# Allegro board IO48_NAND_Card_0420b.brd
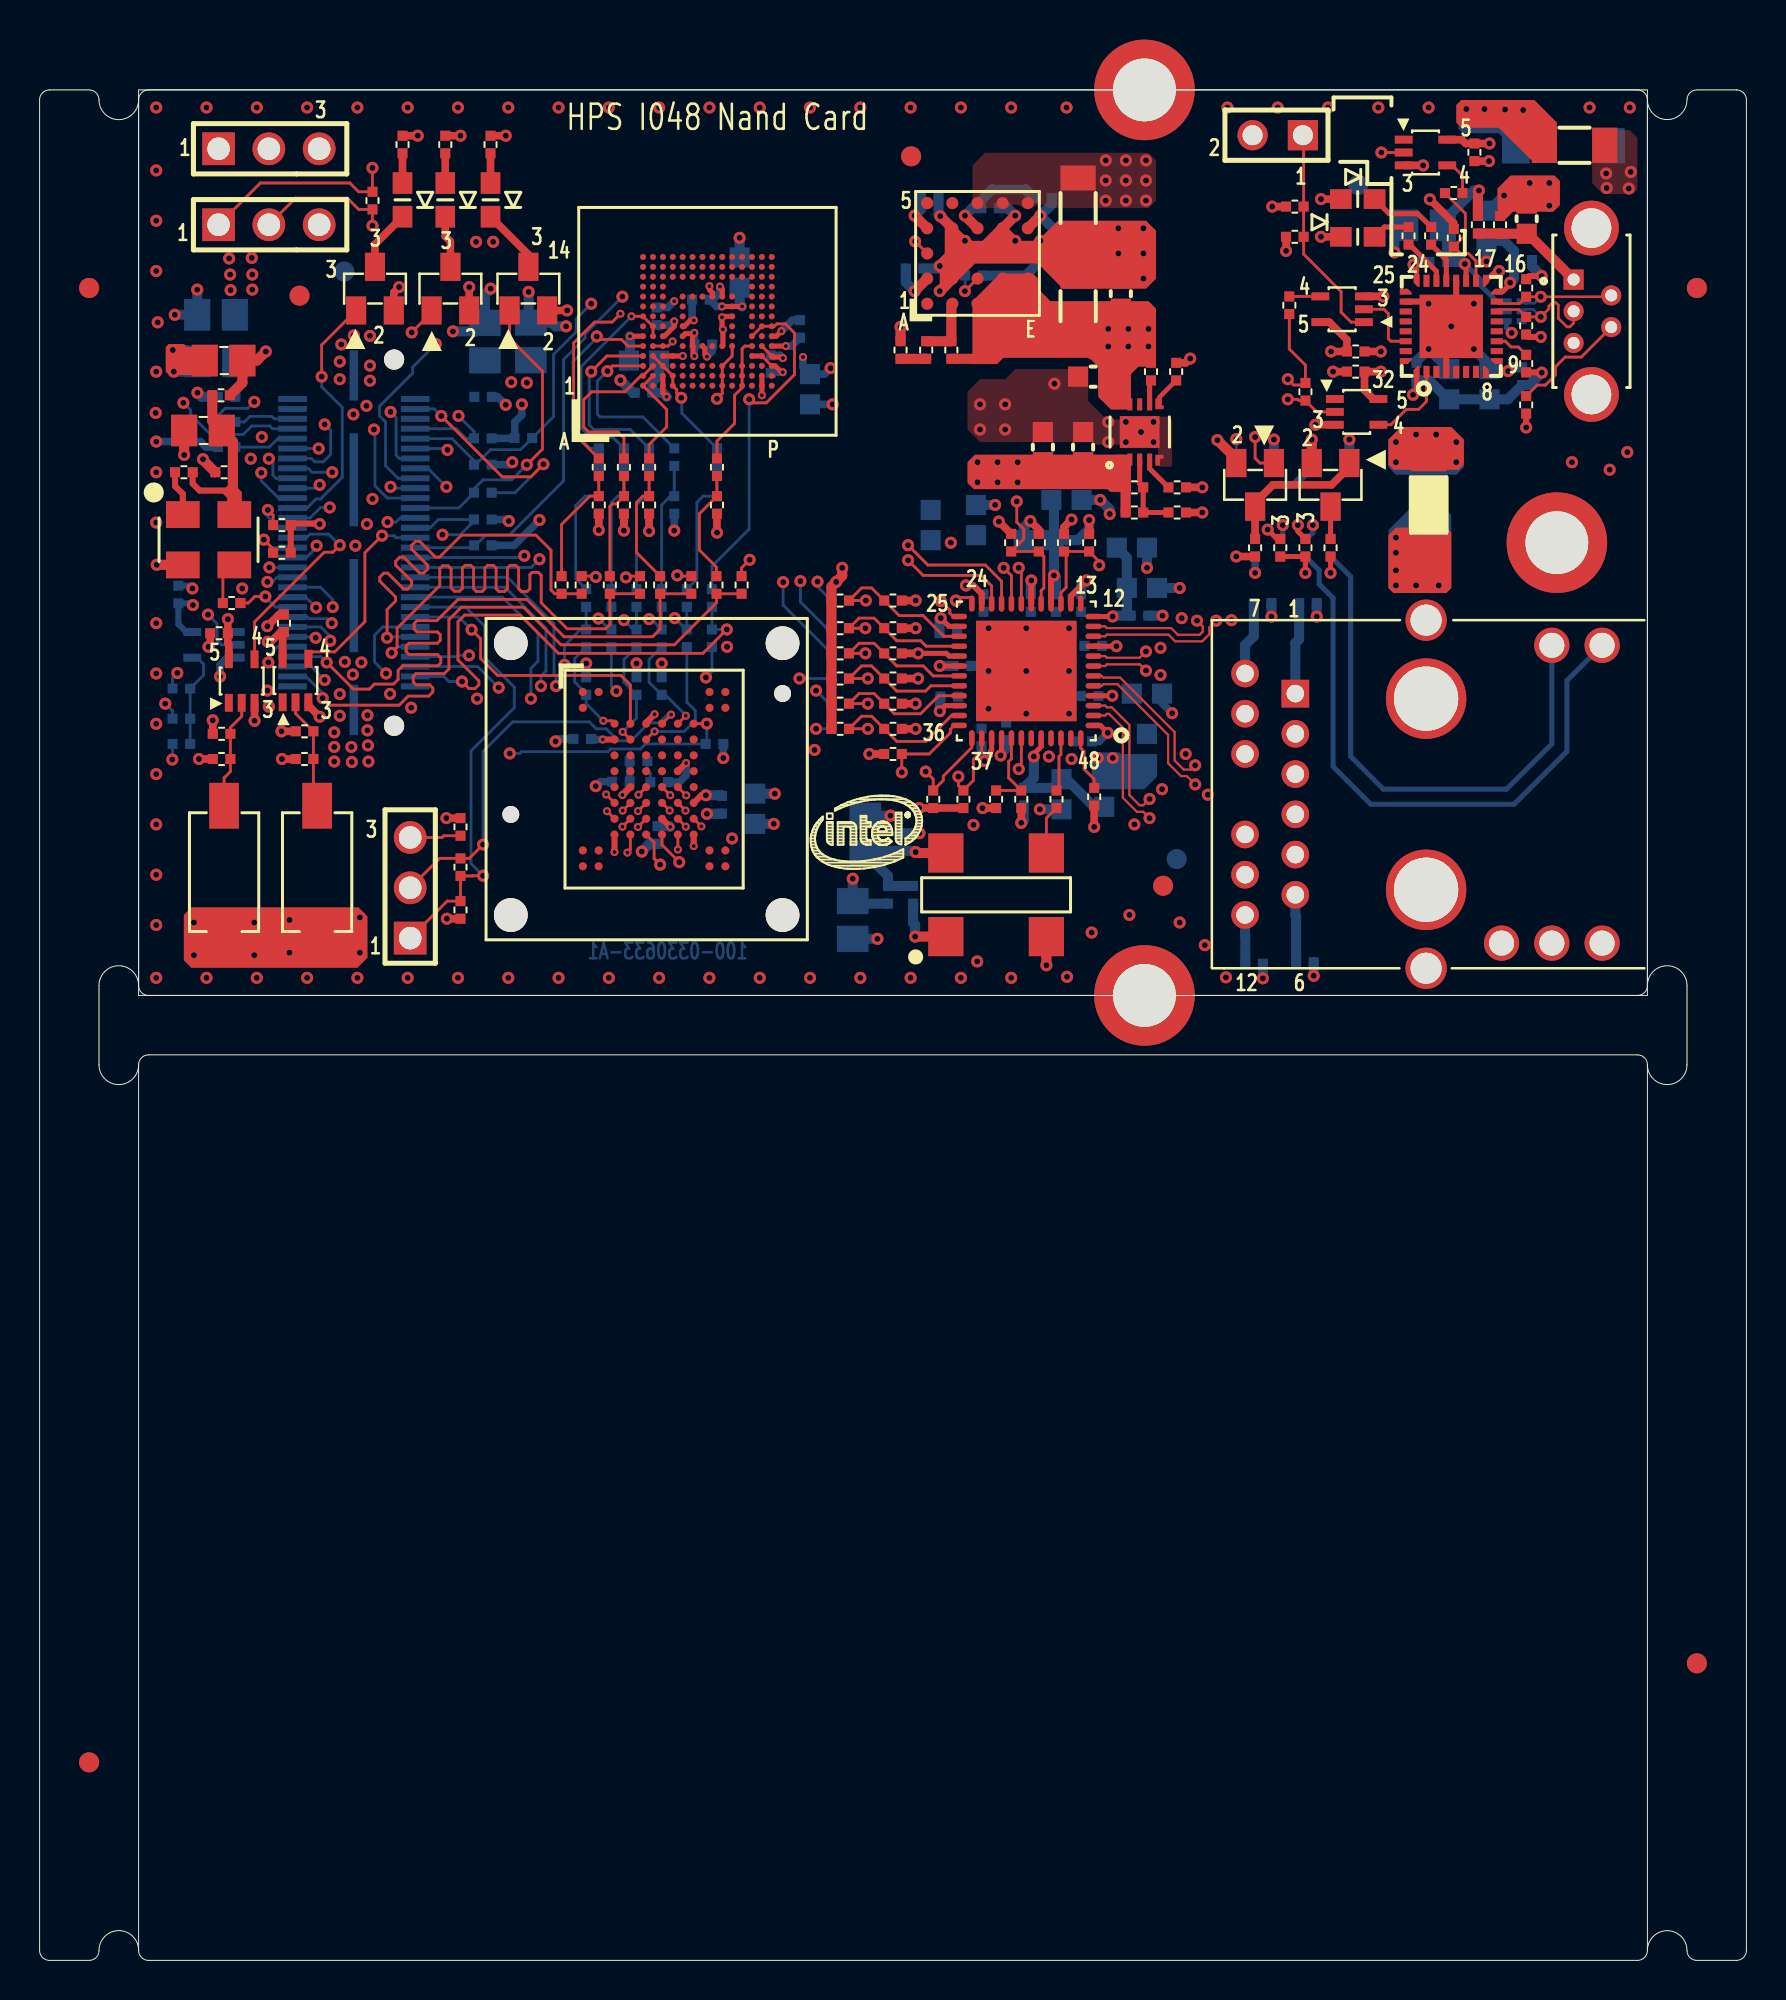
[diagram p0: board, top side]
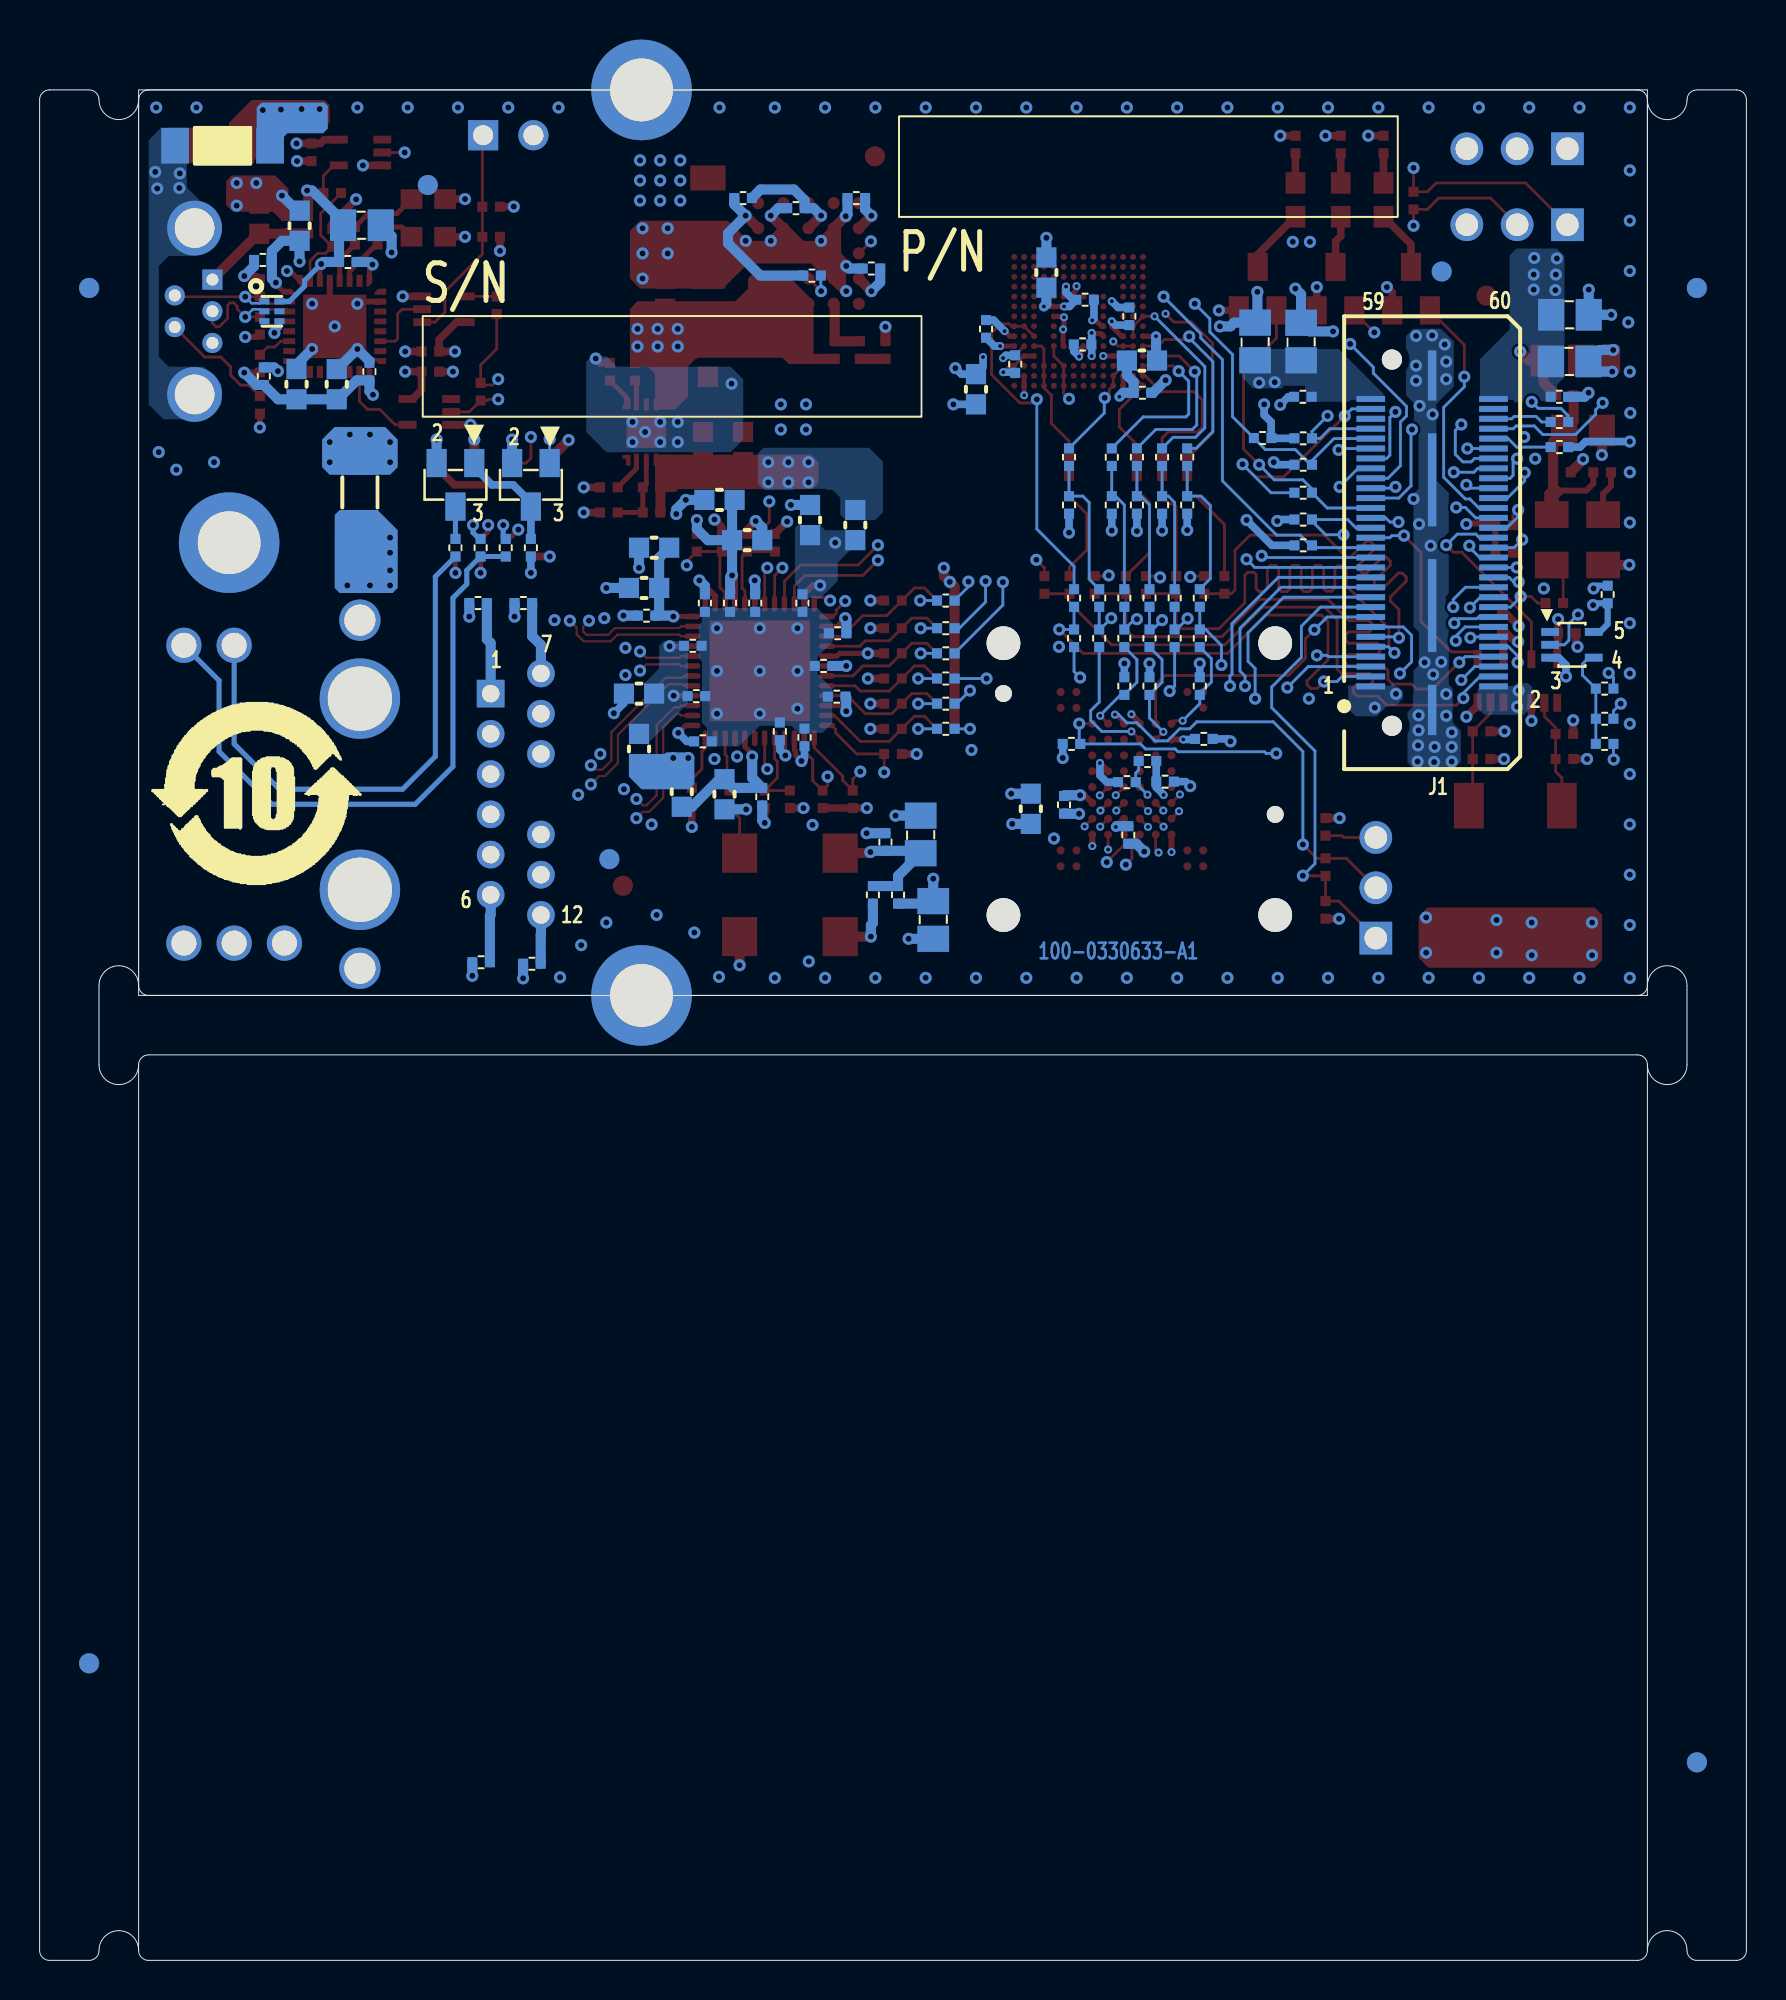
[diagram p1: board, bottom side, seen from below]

Outline 86.2 x 94.44 mm; copper layers: TOP, L2_GND, L3_SIG, L4_GND, L5_PWR, L6_SIG, L7_GND, BOTTOM. Coordinates in mm from the lower left corner of the outline.
Outline path: 5,49.22 arc(4,50.22) 3,49.22 3,45.22 arc(4,44.22) 5,45.22 ; 5,49.22 5,93.94 ; 5,49.22 arc(5.15,48.87) 5.5,48.72 80.7,48.72 arc(81.05,48.87) 81.2,49.22 ; 5,0.5 arc(3.99,1.5) 3,0.48 arc(2.85,0.14) 2.5,0 0.5,0 arc(0.15,0.15) 0,0.5 0,93.94 arc(0.15,94.29) 0.5,94.44 2.5,94.44 arc(2.85,94.29) 3,93.94 arc(4,92.94) 5,93.94 ; 5,0.5 5,45.22 ; 5,0.5 arc(5.15,0.15) 5.5,0 80.7,0 arc(81.05,0.15) 81.2,0.5 ; 5,93.94 arc(5.15,94.29) 5.5,94.44 80.7,94.44 arc(81.05,94.29) 81.2,93.94 ; 5,45.22 arc(5.15,45.57) 5.5,45.72 80.7,45.72 arc(81.05,45.57) 81.2,45.22 ; 81.2,93.94 81.2,49.22 ; 81.2,93.94 arc(82.21,92.94) 83.2,93.96 arc(83.35,94.3) 83.7,94.44 85.7,94.44 arc(86.05,94.29) 86.2,93.94 86.2,0.5 arc(86.05,0.15) 85.7,0 83.7,0 arc(83.35,0.15) 83.2,0.5 arc(82.2,1.5) 81.2,0.5 ; 81.2,45.22 81.2,0.5 ; 81.2,45.22 arc(82.2,44.22) 83.2,45.22 83.2,49.22 arc(82.2,50.22) 81.2,49.22 ; 5,94.44 5,48.72 81.2,48.72 81.2,94.44 5,94.44

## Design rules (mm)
net group ENET_1.8V_DVDDH: nets E_RXD2 ENET_RXD2
net group ENET_RX_CLK: nets E_RX_CLK ENET_RX_CLK
net group ENET_RX_DV: nets E_RX_DV ENET_RX_DV
net group ENET_RXD0: nets E_RXD0 ENET_RXD0
net group ENET_RXD1: nets E_RXD1 ENET_RXD1
net group ENET_RXD3: nets E_RXD3 ENET_RXD3
net group MDI_HPS_N0: nets MDI_HPS_N0 MDI_HPS_P0
net group MDI_HPS_N1: nets MDI_HPS_N1 MDI_HPS_P1
net group MDI_HPS_N2: nets MDI_HPS_N2 MDI_HPS_P2
net group MDI_HPS_N3: nets MDI_HPS_N3 MDI_HPS_P3
net group UART_X: nets UART_RX UART_TX
net group UART_X_LED: nets UART_RX_LED UART_TX_LED
net group USB_UART_DM: nets USB_UART_DM USB_UART_DP
net group EMMC_CLK: nets EMMC_CLK NAND_ADQ0 NAND_ADQ0_EMMC_CLK
net group EMMC_CMD: nets EMMC_CMD EMMC_COMMAND NAND_ADQ1 NAND_ADQ1_EMMC_CMD
net group EMMC_D0: nets EMMC_D0 EMMC_DAT0 NAND_WEN NAND_WEN_EMMC_D0
net group EMMC_D1: nets EMMC_D1 EMMC_DAT1 NAND_REN NAND_REN_EMMC_D1
net group EMMC_D2: nets EMMC_D2 EMMC_DAT2 NAND_WPN NAND_WPN_EMMC_D2
net group EMMC_D3: nets EMMC_D3 EMMC_DAT3 NAND_ADQ2 NAND_ADQ2_EMMC_D3
net group EMMC_D4: nets EMMC_D4 EMMC_DAT4 NAND_ADQ3 NAND_ADQ3_EMMC_D4
net group EMMC_D5: nets EMMC_D5 EMMC_DAT5 NAND_CLE NAND_CLE_EMMC_D5
net group EMMC_D6: nets EMMC_D6 EMMC_DAT6 NAND_ADQ4 NAND_ADQ4_EMMC_D6
net group EMMC_D7: nets EMMC_D7 EMMC_DAT7 NAND_ADQ5 NAND_ADQ5_EMMC_D7
net group ENET: nets ENET_INTN
net group POWER: nets LT_INTVCC N134005839 N134232203 N134273619 N134273639 N134279761 N134279929 N134279963 N134279979 N134280029 N134318194

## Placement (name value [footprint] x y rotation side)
C1  4.7uF  [0805]  22.49 81.73 0 bottom
C2  0.1uF  [0402]  22.4 78.95 90 bottom
C3  4.7uF  [0805]  8.93 80.73 90 bottom
C4  0.1uF  [0402]  9.44 78.95 270 bottom
C5  0.01uF  [0402]  61.34 50.32 270 bottom
C6  0.01uF  [0402]  63.9 50.4 270 bottom
C7  0.01uF  [0402]  64.05 68.53 270 bottom
C8  0.01uF  [0402]  61.77 68.53 270 bottom
C11  22uF  [0603]  55.67 69.29 0 bottom
C13  0.1uF  [0402]  55.55 67.9 90 bottom
C15  22uF  [0603]  50.47 71.71 180 bottom
C17  0.1uF  [0402]  51.33 68.53 0 bottom
C18  22uF  [0603]  51.61 58.88 270 bottom
C20  0.1uF  [0402]  49.7 58.75 0 bottom
C23  22uF  [0603]  55.93 63.96 0 bottom
C25  0.1uF  [0402]  53.21 66.37 270 bottom
C26  22uF  [0603]  52.7 76.41 90 top
C28  2.2uF  [0603]  50.67 76.41 90 top
C29  22uF  [0603]  47.29 72.72 90 bottom
C31  0.1uF  [0402]  47.57 61.75 180 bottom
C36  39pF  [0402]  75.08 84.44 180 top
C37  39pF  [0402]  75.08 82.54 0 top
C38  0.1uF  [0402]  74.93 85.85 90 bottom
C39  2.2uF  [0603]  73.07 87.58 90 bottom
C40  0.1uF  [0402]  69.54 80.22 180 bottom
C41  2.2uF  [0603]  71.19 79.58 90 bottom
C42  0.1uF  [0402]  70.63 85.75 270 bottom
C43  4.7uF  [0805]  69.92 87.61 90 bottom
C44  0.01uF  [0402]  73.76 87.63 0 top
C45  0.1uF  [0402]  31.21 56.82 0 bottom
C46  0.1uF  [0402]  34.46 58.35 0 bottom
C47  0.1uF  [0402]  27.4 61.67 270 bottom
C48  0.1uF  [0402]  29.36 59.51 270 bottom
C49  1uF  [0603]  30.53 80.77 180 bottom
C50  0.1uF  [0402]  30.5 79.15 270 bottom
C51  2.2uF  [0603]  35.35 85.22 90 bottom
C52  0.22uF  [0402]  33.4 83.85 90 bottom
C53  2.2uF  [0603]  38.91 79.33 270 bottom
C54  0.22uF  [0402]  31.16 83.01 0 bottom
C55  0.1uF  [0402]  13.38 60.66 90 top
C56  0.1uF  [0402]  9.19 60.66 90 top
C59  0.1uF  [0402]  72.46 91.29 0 top
C70  0.1uF  [0402]  12.34 67.52 180 top
C76  2.2uF  [0603]  54.61 84.15 90 top
C900  100pF  [0402]  46.05 81.31 180 top
C909  0.1uF  [0402]  7.01 68.96 0 bottom
C914  22uF  [0603]  73.22 79.58 90 bottom
C915  22uF  [0603]  75.1 87.94 90 top
C917  10uF  [1206]  52.45 88.47 270 top
C922  0.01uF  [0402]  44.19 85.42 270 bottom
C924  10uF  [C0805]  41.07 52.53 180 bottom
C925  0.1uF  [0402]  43.48 56.47 180 bottom
C927  10uF  [C0805]  41.7 56.85 0 bottom
C928  22uF  [0603]  53.21 79.96 180 top
C929  1nF  [0402]  57.4 80.22 0 top
C930  120pF  [0402]  55.29 74.37 270 top
C931  0.1uF  [0402]  53.03 63.83 270 bottom
C932  0.1uF  [0402]  46.61 65.36 90 bottom
C933  0.1uF  [0402]  45.89 67.01 90 bottom
C934  0.1uF  [0402]  47.67 68.53 0 bottom
C935  0.1uF  [0402]  50.06 68.53 0 bottom
C936  0.1uF  [0402]  52.6 68.53 0 bottom
C937  0.1uF  [0402]  52.7 61.55 270 bottom
C938  0.1uF  [0402]  45.94 63.81 90 bottom
C939  0.1uF  [0402]  48.81 62.05 180 bottom
C940  1000PF  [1808]  76.96 91.62 0 bottom
C942  1000PF  [1808]  70.15 73.48 270 top
C943  0.1uF  [0402]  66.47 80.22 270 top
C944  0.1uF  [0402]  66.47 81.23 90 top
C949  47uF  [1206]  52.45 83.52 270 top
C953  0.1uF  [0402]  9.32 75.14 90 top
C954  10uF  [C0805]  9.29 80.77 270 top
C955  10uF  [C0805]  8.25 77.24 270 top
C956  0.1uF  [0402]  9.06 67.01 270 top
C957  2.2uF  [0603]  36.14 58.14 270 bottom
C958  0.22uF  [0402]  33.52 81.59 270 bottom
C959  0.22uF  [0402]  36.93 80.6 0 bottom
C960  0.22uF  [0402]  38.4 82.37 0 bottom
C961  4.7uF  [0805]  24.81 81.74 0 bottom
C962  4.7uF  [0805]  8.91 83.09 90 bottom
C964  0.1uF  [0402]  63.93 71.33 0 top
C965  0.1uF  [0402]  63.93 71.33 0 bottom
D1  GREEN_LED  [LED_0603]  66.57 87.02 0 top
D2  GREEN_LED  [LED_0603]  66.57 88.93 0 top
D3  GREEN_LED  [LED_0603]  20.49 88.89 270 top
D4  GREEN_LED  [LED_0603]  18.33 88.89 270 top
D5  GREEN_LED  [LED_0603]  22.77 88.89 270 top
J1  QTH-030-02-L-D-A  [QTH-030]  15.87 71.58 90 bottom
J2  HEADER, 1x3-PIN  [CONN_TSW_103_07_L_S]  9.04 91.47 0 top
J3  ENET_L829-1J1T-43  [BEL_L829-1J1T-43]  63.42 63.96 270 top
J7  USB MINI-B-SMT Vertical  [MINI_USB_SMTB]  78.37 83.26 90 top
J9  CON2  [HDR2X1_100MIL]  63.8 92.15 180 top
J10  HEADER, 1x3-PIN  [CONN_TSW_103_07_L_S]  9.04 87.63 0 top
J11  HEADER, 1x3-PIN  [CONN_TSW_103_07_L_S]  18.72 51.62 90 top
L1  3A, 30 Ohm FB  [IND_0603]  55.16 71.33 180 bottom
L2  3A, 30 Ohm FB  [IND_0603]  51.86 73.74 180 bottom
L3  3A, 30 Ohm FB  [IND_0603]  53.77 59.01 270 bottom
L4  3A, 30 Ohm FB  [IND_0603]  55.93 61.17 90 bottom
L5  3A, 30 Ohm FB  [IND_0603]  45 72.47 270 bottom
L6  742792780  [0402]  72.64 87.63 0 top
L7  742792780  [0402]  42.85 53.8 0 bottom
L8  742792780  [0402]  9.17 79.02 270 top
L10  742792780  [0402]  65.2 71.33 180 bottom
L11  742792780  [0402]  65.2 71.33 0 top
NOREF  #  [unnamed]  55.8 94.44 0 top
NOREF#2  -  [unnamed#2]  44.01 91.09 0 top
NOREF#3  -  [unnamed#2]  2.5 84.44 0 top
NOREF#4  -  [unnamed#2]  83.7 84.44 0 top
NOREF#5  -  [unnamed#2]  13.13 84.05 0 top
NOREF#6  -  [unnamed#2]  83.7 15 0 top
NOREF#7  #  [unnamed]  55.8 48.72 0 top
NOREF#8  -  [unnamed#2]  56.74 54.26 0 top
NOREF#9  #  [unnamed]  76.63 71.58 0 top
NOREF#10  -  [unnamed#2]  2.5 10 0 top
NOREF#11  -  [unnamed#2]  83.7 15 180 bottom
NOREF#12  -  [unnamed#2]  15.39 85.27 180 bottom
NOREF#13  -  [unnamed#2]  66.59 89.64 180 bottom
NOREF#14  -  [unnamed#2]  57.43 55.6 180 bottom
NOREF#15  -  [unnamed#2]  2.5 10 180 bottom
NOREF#16  -  [unnamed#2]  2.5 84.44 180 bottom
NOREF#17  -  [unnamed#2]  83.7 84.44 180 bottom
Q1  FDV305N  [SOT23]  20.75 84.41 0 top
Q2  FDV305N  [SOT23]  16.94 84.41 0 top
Q3  FDV305N  [SOT23]  24.68 84.41 0 top
Q4  FDV305N  [SOT23]  61.39 74.5 180 top
Q5  FDV305N  [SOT23]  65.2 74.5 180 top
Q6  FDV305N  [SOT23]  61.39 74.5 0 bottom
Q7  FDV305N  [SOT23]  65.2 74.5 0 bottom
R1  0  [0402]  9.44 76.41 90 bottom
R2  4.7K  [0402]  43.1 60.91 90 top
R4  4.7K  [0402]  45.13 58.63 180 top
R6  33  [0402]  40.43 62.18 90 bottom
R7  4.7K  [0402]  46.66 58.63 180 top
R8  220  [0402]  62.66 71.33 180 bottom
R9  33  [0402]  40.43 63.45 90 bottom
R10  33  [0402]  40.43 64.72 90 bottom
R11  33  [0402]  40.43 65.99 90 bottom
R12  33  [0402]  40.43 67.26 90 bottom
R13  33  [0402]  40.43 68.66 90 bottom
R14  220  [0402]  62.66 71.33 0 top
R15  12.1K  [0402]  53.26 58.75 0 top
R16  DNI  [0402]  53.01 71.58 0 top
R17  4.7K  [0402]  51.74 71.58 180 top
R18  10K  [0402]  44.12 53.8 180 bottom
R19  33  [0402]  51.35 58.63 180 top
R20  DNI  [0402]  49.07 71.58 0 top
R21  4.7K  [0402]  50.47 71.58 180 top
R23  4.7K  [0402]  40.43 68.66 90 top
R24  DNI  [0402]  43.1 68.66 90 top
R25  4.7K  [0402]  40.43 67.26 90 top
R26  DNI  [0402]  43.1 67.26 90 top
R27  4.7K  [0402]  40.43 65.99 90 top
R28  DNI  [0402]  43.1 65.99 90 top
R29  4.7K  [0402]  40.43 64.72 90 top
R30  DNI  [0402]  43.1 64.72 90 top
R31  DNI  [0402]  40.43 63.45 90 top
R32  4.7K  [0402]  43.1 63.45 90 top
R33  4.7K  [0402]  40.43 62.18 90 top
R34  DNI  [0402]  43.1 62.18 90 top
R35  4.7K  [0402]  48.31 58.63 180 top
R36  DNI  [0402]  49.58 58.63 0 top
R39  1.87K  [0402]  57.45 73.1 270 top
R42  0  [0402]  74.88 79.99 180 bottom
R46  0  [0402]  75.08 78.54 0 top
R48  220  [0402]  69.13 87.07 180 top
R49  220  [0402]  70.28 87.07 180 top
R50  10K  [0402]  75.08 80.62 0 top
R52  0  [0402]  33.96 66.75 180 bottom
R53  0  [0402]  33.96 68.79 0 bottom
R54  0  [0402]  34.18 69.45 180 top
R55  0  [0402]  35.45 69.45 180 top
R56  0  [0402]  32.91 69.45 180 top
R57  0  [0402]  31.34 69.45 180 top
R58  0  [0402]  30.32 69.45 180 top
R59  0  [0402]  28.8 69.45 180 top
R60  0  [0402]  27.38 69.45 180 top
R62  0  [0402]  26.36 69.45 180 top
R64  0  [0402]  28.88 66.75 180 bottom
R65  0  [0402]  28.88 68.79 0 bottom
R66  0  [0402]  27.61 66.75 180 bottom
R67  0  [0402]  27.61 68.79 0 bottom
R68  0  [0402]  31.42 66.75 180 bottom
R69  0  [0402]  31.42 68.79 0 bottom
R72  0  [0402]  30.15 66.75 180 bottom
R74  0  [0402]  30.15 68.79 0 bottom
R77  0  [0402]  32.69 66.75 180 bottom
R79  0  [0402]  32.69 68.79 0 bottom
R83  10K  [0402]  34.21 73.48 0 top
R86  220  [0402]  20.49 91.68 0 top
R87  220  [0402]  18.33 91.68 0 top
R88  220  [0402]  22.77 91.68 0 top
R89  10K  [0402]  13.38 62.05 270 top
R90  10K  [0402]  9.19 61.93 270 top
R91  10K  [0402]  7.29 75.14 270 top
R102  10K  [0402]  27.61 64.34 0 bottom
R103  10K  [0402]  21.26 53.04 0 top
R104  10K  [0402]  30.15 64.34 0 bottom
R105  10K  [0402]  31.42 64.34 0 bottom
R456  13.3K  [0402]  44.78 81.31 180 top
R667  324K  [R0402]  44.95 88.98 90 bottom
R668  0  [0402]  43.48 81.31 0 top
R671  10K  [0402]  47.19 85.07 270 bottom
R675  4.7K  [0402]  22.38 76.85 90 bottom
R681  DNI  [0402]  9.44 77.68 90 bottom
R682  DNI  [0402]  22.38 74.1 90 bottom
R686  4.7K  [0402]  22.38 72.75 90 bottom
R687  4.7K  [0402]  22.38 71.44 90 bottom
R688  4.7K  [0402]  12.24 71.07 270 top
R698  1.00K  [0402]  22.38 75.52 90 bottom
R699  2.61K  [0402]  55.29 73.1 90 top
R5256  4.7K  [0402]  12.24 72.47 270 top
R5257  1.00K  [0402]  31.29 59.49 270 bottom
R5258  10K  [0402]  34.08 61.42 270 bottom
R5259  1.00K  [0402]  50.67 88.98 90 bottom
R5262  4.7K  [0402]  56.13 80.22 180 top
R5265  4.7K  [0402]  57.45 74.37 90 top
R5266  1M  [1206]  77.52 91.65 180 top
R5268  1M  [1206]  70.02 74.12 90 bottom
R5269  1.00K  [0402]  63.39 87.02 90 top
R5270  DNI  [0402]  71.42 89.23 270 top
R5271  4.7K  [0402]  71.42 86.97 0 top
R5275  DNI  [0402]  48 88.47 90 bottom
R5276  33  [0402]  7.16 61.42 90 bottom
R5277  33  [0402]  7.16 62.69 90 bottom
R5278  33  [0402]  7.16 64.21 90 bottom
R5279  10K  [0402]  32.05 73.48 180 bottom
R5280  10K  [0402]  28.24 73.48 180 bottom
R5281  10K  [0402]  30.78 73.48 180 bottom
R5282  10K  [0402]  30.78 73.48 0 top
R5283  10K  [0402]  29.51 73.48 0 top
R5284  10K  [0402]  34.21 73.48 180 bottom
R5285  10K  [0402]  28.24 73.48 0 top
R5286  10K  [0402]  29.51 73.48 180 bottom
R5287  DNI  [0402]  63.39 88.55 270 top
R5288  DNI  [0402]  63.93 79.2 180 top
R5289  33  [0402]  9.7 68.53 90 top
R5300  33  [0402]  63.12 83.57 180 top
R5301  33  [0402]  32.05 75.9 0 bottom
R5302  33  [0402]  30.78 75.9 0 bottom
R5303  33  [0402]  28.24 75.9 0 bottom
R5304  33  [0402]  30.78 75.39 180 top
R5305  33  [0402]  29.51 75.39 180 top
R5306  33  [0402]  34.21 75.9 0 bottom
R5307  33  [0402]  28.24 75.39 180 top
R5308  33  [0402]  29.51 75.9 0 bottom
R5309  33  [0402]  34.21 75.39 180 top
R5310  DNI  [0402]  30.25 60.56 270 bottom
R5311  1.00K  [0402]  61.39 71.33 180 top
R5312  1.00K  [0402]  61.39 71.33 0 bottom
R5313  10K  [0402]  21.26 57.23 0 top
R5314  DNI  [0402]  16.81 88.85 0 top
R5315  DNI  [0402]  21.26 55.2 180 top
R5316  DNI  [0402]  24.43 76.86 270 bottom
S1  PB Switch  [WURTH_6X3P5_TACT_SWITCH]  14.02 54.94 90 top
S2  PB Switch  [WURTH_6X3P5_TACT_SWITCH]  9.32 54.94 90 top
U1  KSZ9031RN  [QFN48]  49.83 65.1 180 top
U5  FT232R  [QFN32-FTDI]  71.29 82.5 90 top
U6  TPD4S012DRYR  [SON6]  74.47 83.26 270 bottom
U7  MT29F8G16ADBDAH4-AIT:D  [VFBGA63_SOCKET]  31.03 59.64 0 top
U8  MTFC8GAKAJCN-4M IT  [VFBGA-153]  33.73 82.76 90 top
U14  SN74AUP1G17DCK  [SC70_TI]  12.92 64.62 0 top
U15  LTM4623EY#PBF  [BGA25]  47.37 86.18 90 top
U62  EY1501DI-ADJ  [DFN-10]  55.56 77.17 90 top
U63  SN74AUP1G126DCK  [SC70_TI]  65.78 83.37 90 top
U64  SN74AUP1T17DCKR  [SC70_TI]  69.99 91.28 270 top
U65  SN74AUP1T17DCKR  [SC70_TI]  66.52 78.18 270 top
U68  SN74AUP1G17DCK  [SC70_TI]  8.81 66.42 270 bottom
U69  SN74AUP1G17DCK  [SC70_TI]  10.21 64.59 0 top
Y1  25MHz  [OSC3250]  8.53 71.73 0 top
Y2  25MHz  [OSC7050]  48.31 53.8 0 top

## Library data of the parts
C1-C8 C13 C17 C20 C25 C31 C38 C40 C42-C48 C50 C52 C54-C56 C59 C70 C900 C909 C922 C924 C925 C927 C929-C939 C943 C944 C953-C956 C958-C962 C964 C965 = CAP: Tolerance: TOL; User Part Number: PART#
C11 C15 C18 C23 C26 C28 C29 C39 C41 C49 C51 C53 C76 C914 C915 C928 C957 = CAP: User Part Number: *; Tolerance: *
C36 C37 = Cap 39PF 5% 50V 0402: Tolerance: TOL; User Part Number: PART#
C917 C949 = CAP: Tolerance: *; User Part Number: *
C940 C942 = CAP: Tolerance: ?; User Part Number: CC4520R01A
D1-D5 = LED_WURTH: Tolerance: *; User Part Number: *
J1 = HEADER 30X2_0
J2 J10 J11 = HEADER, 1x3-PIN: User Part Number: *
J3 = ENET_L829-1J1T-43_2: Tolerance: *; User Part Number: *
J7 = USB_MINI_B_SMT
J9 = CON2: User Part Number: *
L1-L5 = IND Ferrite 0603 3A/30 Ohms: Tolerance: *; User Part Number: *
L6-L8 L10 L11 = BEAD_FERRITE_SM: Tolerance: TOL; User Part Number: PART#
NOREF = -: User Part Number: ***********; Tolerance: ?
NOREF#7 NOREF#9 = -: Tolerance: ?; User Part Number: ***********
Q1-Q7 = NMOS_3Pin: Tolerance: *; User Part Number: *
R1 R2 R4 R7 R8 R14-R21 R23 R24 R26-R36 R39 R42 R46 R48-R50 R83 R86-R91 R102-R105 R668 R671 R675 R681 R682 R686-R688 R698 R5256-R5259 R5262 R5265 R5269-R5271 R5275-R5289 R5300 R5310-R5316 = RESISTOR: Tolerance: TOL; User Part Number: PART#
R6 R9-R13 R5301-R5309 = RESISTOR: Tolerance: TOL; User Part Number: PART#; signal model: RESISTOR_0402_33_33
R25 = RESISTOR: Tolerance: TOL; User Part Number: PART#; signal model: RESISTOR_0402_4.7K_4.7K
R52-R60 R62 R64-R69 R72 R74 R77 R79 = RESISTOR: Tolerance: TOL; User Part Number: PART#; signal model: RESISTOR_0402_0_0
R456 = RESISTOR_0402: Tolerance: TOL; User Part Number: PART#
R667 = Resistor, 0402: User Part Number: PART#; Tolerance: TOL
R699 = R: Tolerance: TOL; User Part Number: PART#
R5266 R5268 = RESISTOR: Tolerance: *; User Part Number: *
S1 S2 = TS-A02SA-2-S100_0: User Part Number: *
U1 = KSZ9031RN_4: User Part Number: *
U5 = FT232R_2: User Part Number: *
U6 = TPD4S012DRYR: User Part Number: *
U7 = MT29F8G16ABBCAH4-IT_1
U8 = MTFC8GAKAJCN-4M IT
U14 U64 U65 U68 U69 = SN74AUP1G17DCK
U15 = LTM4623EV#PBF
U62 = EY1501DI-ADJ
U63 = SN74AUP1G126DCK
Y1 = OSC_ALT
Y2 = OSC_ALT: User Part Number: *; Tolerance: *

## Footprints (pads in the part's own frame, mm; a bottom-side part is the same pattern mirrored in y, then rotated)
0402
  rect 0.508x0.508 smd: 1(0,0.445) 2(0,-0.445)
0603
  rect 1.016x1.016 smd: 1(-0.762,0) 2(0.762,0)
0805
  rect 1.6x1.321 smd: 1(0,0.95) 2(0,-0.95)
1206
  rect 1.27x1.778 smd: 1(-1.524,0) 2(1.524,0)
1808
  rect 1.4x1.8 smd: 1(-2.4,0) 2(2.4,0)
BEL_L829-1J1T-43
  round 4.064 hole 3.251: (0.254,6.604) (9.906,6.604)
  rect 1.397x1.397 hole 0.889: 1(0,0)
  round 1.397 hole 0.889: 2(2.032,0) 3(4.064,0) 4(6.096,0) 5(8.128,0) 6(10.16,0) 7(-1.016,-2.54) 8(1.016,-2.54) 9(3.048,-2.54) 10(7.112,-2.54) 11(9.144,-2.54) 12(11.176,-2.54)
  round 1.778 hole 1.27: 13(-2.438,12.954) 14(-2.438,15.494) 15(12.598,10.414) 16(12.598,12.954) 17(12.598,15.494)
  round 2.083 hole 1.575: 18(-3.708,6.604) 19(13.868,6.604)
BGA25
  round 0.61 smd: A1(-2.54,2.54) A2(-1.27,2.54) A3(0,2.54) A4(1.27,2.54) A5(2.54,2.54) B1(-2.54,1.27) B2(-1.27,1.27) B3(0,1.27) B4(1.27,1.27) B5(2.54,1.27) C1(-2.54,0) C2(-1.27,0) C3(0,0) C4(1.27,0) C5(2.54,0) D1(-2.54,-1.27) D2(-1.27,-1.27) D3(0,-1.27) D4(1.27,-1.27) D5(2.54,-1.27) E1(-2.54,-2.54) E2(-1.27,-2.54) E3(0,-2.54) E4(1.27,-2.54) E5(2.54,-2.54)
C0805
  rect 1.6x1.321 smd: 1(0,0.95) 2(0,-0.95)
CONN_TSW_103_07_L_S
  rect 1.651x1.651 hole 1.143: 1(0,0)
  round 1.651 hole 1.143: 2(2.54,0) 3(5.08,0)
DFN-10
  custom 0.104x0.104 smd: 1(-1.425,1) 5(-1.425,-1) 6(1.425,-1) 10(1.425,1)
  rect 0.61x0.254 smd: 2(-1.395,0.5) 3(-1.395,0) 4(-1.395,-0.5) 7(1.395,-0.5) 8(1.395,0) 9(1.395,0.5)
  rect 1.6x2.007 smd: 11(0,0)
HDR2X1_100MIL
  rect 1.524x1.524 hole 1.016: 1(0,0)
  round 1.524 hole 1.016: 2(2.54,0)
IND_0603
  rect 1.016x1.016 smd: 1(-0.762,0) 2(0.762,0)
LED_0603
  rect 1.092x0.991 smd: A(-0.851,0) C(0.851,0)
MINI_USB_SMTB
  rect 1.016x1.016 hole 0.61: 1(1.6,0.9)
  round 1.016 hole 0.61: 2(0.8,-1) 3(0,0.9) 4(-0.8,-1) 5(-1.6,0.9)
  round 2.769 hole 2.007: 6(-4.2,0) 7(4.2,0)
OSC3250
  rect 1.7x1.35 smd: 1(-1.3,1.27) 2(-1.3,-1.27) 3(1.3,-1.27) 4(1.3,1.27)
OSC7050
  rect 1.778x1.981 smd: 1(-2.54,-2.109) 2(2.54,-2.109) 3(2.54,2.109) 4(-2.54,2.109)
QFN32-FTDI
  custom 0.075x0.075 smd: 1(-2.3,1.75) 8(-2.3,-1.75) 9(-1.75,-2.3) 16(1.75,-2.3) 17(2.3,-1.75) 24(2.3,1.75) 25(1.75,2.3) 32(-1.75,2.3)
  rect 0.61x0.305 smd: 2(-2.3,1.25) 3(-2.3,0.75) 4(-2.3,0.25) 5(-2.3,-0.25) 6(-2.3,-0.75) 7(-2.3,-1.25) 18(2.3,-1.25) 19(2.3,-0.75) 20(2.3,-0.25) 21(2.3,0.25) 22(2.3,0.75) 23(2.3,1.25)
  rect 0.305x0.61 smd: 10(-1.25,-2.3) 11(-0.75,-2.3) 12(-0.25,-2.3) 13(0.25,-2.3) 14(0.75,-2.3) 15(1.25,-2.3) 26(1.25,2.3) 27(0.75,2.3) 28(0.25,2.3) 29(-0.25,2.3) 30(-0.75,2.3) 31(-1.25,2.3)
  rect 3.2x3.2 smd: 33(0,0)
QFN48
  oval 0.813x0.279 smd: 1(-3.4,2.75) 2(-3.4,2.25) 3(-3.4,1.75) 4(-3.4,1.25) 5(-3.4,0.75) 6(-3.4,0.25) 7(-3.4,-0.25) 8(-3.4,-0.75) 9(-3.4,-1.25) 10(-3.4,-1.75) 11(-3.4,-2.25) 12(-3.4,-2.75) 25(3.4,-2.75) 26(3.4,-2.25) 27(3.4,-1.75) 28(3.4,-1.25) 29(3.4,-0.75) 30(3.4,-0.25) 31(3.4,0.25) 32(3.4,0.75) 33(3.4,1.25) 34(3.4,1.75) 35(3.4,2.25) 36(3.4,2.75)
  oval 0.279x0.813 smd: 13(-2.75,-3.4) 14(-2.25,-3.4) 15(-1.75,-3.4) 16(-1.25,-3.4) 17(-0.75,-3.4) 18(-0.25,-3.4) 19(0.25,-3.4) 20(0.75,-3.4) 21(1.25,-3.4) 22(1.75,-3.4) 23(2.25,-3.4) 24(2.75,-3.4) 37(2.75,3.4) 38(2.25,3.4) 39(1.75,3.4) 40(1.25,3.4) 41(0.75,3.4) 42(0.25,3.4) 43(-0.25,3.4) 44(-0.75,3.4) 45(-1.25,3.4) 46(-1.75,3.4) 47(-2.25,3.4) 48(-2.75,3.4)
  rect 5.08x5.08 smd: 49(0,0)
QTH-030
  round 1.016 hole 1.016 unplated: (-9.246,2.032) (9.246,2.032)
  rect 0.305x1.448 smd: 1(-7.256,3.099) 2(-7.256,-3.099) 3(-6.755,3.099) 4(-6.755,-3.099) 5(-6.255,3.099) 6(-6.255,-3.099) 7(-5.754,3.099) 8(-5.754,-3.099) 9(-5.254,3.099) 10(-5.254,-3.099) 11(-4.754,3.099) 12(-4.754,-3.099) 13(-4.253,3.099) 14(-4.253,-3.099) 15(-3.753,3.099) 16(-3.753,-3.099) 17(-3.252,3.099) 18(-3.252,-3.099) 19(-2.752,3.099) 20(-2.752,-3.099) 21(-2.252,3.099) 22(-2.252,-3.099) 23(-1.751,3.099) 24(-1.751,-3.099) 25(-1.251,3.099) 26(-1.251,-3.099) 27(-0.751,3.099) 28(-0.751,-3.099) 29(-0.25,3.099) 30(-0.25,-3.099) 31(0.25,3.099) 32(0.25,-3.099) 33(0.751,3.099) 34(0.751,-3.099) 35(1.251,3.099) 36(1.251,-3.099) 37(1.751,3.099) 38(1.751,-3.099) 39(2.252,3.099) 40(2.252,-3.099) 41(2.752,3.099) 42(2.752,-3.099) 43(3.252,3.099) 44(3.252,-3.099) 45(3.753,3.099) 46(3.753,-3.099) 47(4.253,3.099) 48(4.253,-3.099) 49(4.754,3.099) 50(4.754,-3.099) 51(5.254,3.099) 52(5.254,-3.099) 53(5.754,3.099) 54(5.754,-3.099) 55(6.255,3.099) 56(6.255,-3.099) 57(6.755,3.099) 58(6.755,-3.099) 59(7.256,3.099) 60(7.256,-3.099)
  rect 2.54x0.432 smd: 61(-8.445,0) 64(8.445,0)
  rect 4.699x0.432 smd: 62(-3.175,0) 63(3.175,0)
R0402
  rect 0.508x0.508 smd: 1(0,0.445) 2(0,-0.445)
SC70_TI
  rect 0.4x0.9 smd: 1(-0.65,-1.1) 2(0,-1.1) 3(0.65,-1.1) 4(0.65,1.1) 5(-0.65,1.1)
SON6
  rect 0.305x0.508 smd: 1(-0.5,-0.379) 2(0,-0.379) 3(0.5,-0.379) 4(0.5,0.379) 5(0,0.379) 6(-0.5,0.379)
SOT23
  rect 1.016x1.422 smd: 1(-0.95,-1.1) 2(0.95,-1.1) 3(0,1.1)
unnamed
  round 5.08 hole 3.175: 1(0,0)
unnamed#2
  round 1.016 smd: (0,0)
VFBGA63_SOCKET
  round 1.702 hole 1.702 unplated: (-7.237,6.863) (-7.237,-6.863) (6.487,6.863) (6.487,-6.863)
  round 0.85 hole 0.85 unplated: (-7.237,-1.783) (6.487,4.323)
  round 0.406 smd: A1(-3.6,4.4) A2(-2.8,4.4) A9(2.8,4.4) A10(3.6,4.4) B1(-3.6,3.6) B9(2.8,3.6) B10(3.6,3.6) C3(-2,2.8) C4(-1.2,2.8) C5(-0.4,2.8) C6(0.4,2.8) C7(1.2,2.8) C8(2,2.8) D3(-2,2) D4(-1.2,2) D5(-0.4,2) D6(0.4,2) D7(1.2,2) D8(2,2) E3(-2,1.2) E4(-1.2,1.2) E5(-0.4,1.2) E6(0.4,1.2) E7(1.2,1.2) E8(2,1.2) F3(-2,0.4) F4(-1.2,0.4) F5(-0.4,0.4) F6(0.4,0.4) F7(1.2,0.4) F8(2,0.4) G3(-2,-0.4) G4(-1.2,-0.4) G5(-0.4,-0.4) G6(0.4,-0.4) G7(1.2,-0.4) G8(2,-0.4) H3(-2,-1.2) H4(-1.2,-1.2) H5(-0.4,-1.2) H6(0.4,-1.2) H7(1.2,-1.2) H8(2,-1.2) J3(-2,-2) J4(-1.2,-2) J5(-0.4,-2) J6(0.4,-2) J7(1.2,-2) J8(2,-2) K3(-2,-2.8) K4(-1.2,-2.8) K5(-0.4,-2.8) K6(0.4,-2.8) K7(1.2,-2.8) K8(2,-2.8) L1(-3.6,-3.6) L2(-2.8,-3.6) L9(2.8,-3.6) L10(3.6,-3.6) M1(-3.6,-4.4) M2(-2.8,-4.4) M9(2.8,-4.4) M10(3.6,-4.4)
VFBGA-153
  round 0.305 smd: A1(-3.25,3.25) A2(-2.75,3.25) A3(-2.25,3.25) A4(-1.75,3.25) A5(-1.25,3.25) A6(-0.75,3.25) A7(-0.25,3.25) A8(0.25,3.25) A9(0.75,3.25) A10(1.25,3.25) A11(1.75,3.25) A12(2.25,3.25) A13(2.75,3.25) A14(3.25,3.25) B1(-3.25,2.75) B2(-2.75,2.75) B3(-2.25,2.75) B4(-1.75,2.75) B5(-1.25,2.75) B6(-0.75,2.75) B7(-0.25,2.75) B8(0.25,2.75) B9(0.75,2.75) B10(1.25,2.75) B11(1.75,2.75) B12(2.25,2.75) B13(2.75,2.75) B14(3.25,2.75) C1(-3.25,2.25) C2(-2.75,2.25) C3(-2.25,2.25) C4(-1.75,2.25) C5(-1.25,2.25) C6(-0.75,2.25) C7(-0.25,2.25) C8(0.25,2.25) C9(0.75,2.25) C10(1.25,2.25) C11(1.75,2.25) C12(2.25,2.25) C13(2.75,2.25) C14(3.25,2.25) D1(-3.25,1.75) D2(-2.75,1.75) D3(-2.25,1.75) D4(-1.75,1.75) D12(2.25,1.75) D13(2.75,1.75) D14(3.25,1.75) E1(-3.25,1.25) E2(-2.75,1.25) E3(-2.25,1.25) E5(-1.25,1.25) E6(-0.75,1.25) E7(-0.25,1.25) E8(0.25,1.25) E9(0.75,1.25) E10(1.25,1.25) E12(2.25,1.25) E13(2.75,1.25) E14(3.25,1.25) F1(-3.25,0.75) F2(-2.75,0.75) F3(-2.25,0.75) F5(-1.25,0.75) F10(1.25,0.75) F12(2.25,0.75) F13(2.75,0.75) F14(3.25,0.75) G1(-3.25,0.25) G2(-2.75,0.25) G3(-2.25,0.25) G5(-1.25,0.25) G10(1.25,0.25) G12(2.25,0.25) G13(2.75,0.25) G14(3.25,0.25) H1(-3.25,-0.25) H2(-2.75,-0.25) H3(-2.25,-0.25) H5(-1.25,-0.25) H10(1.25,-0.25) H12(2.25,-0.25) H13(2.75,-0.25) H14(3.25,-0.25) J1(-3.25,-0.75) J2(-2.75,-0.75) J3(-2.25,-0.75) J5(-1.25,-0.75) J10(1.25,-0.75) J12(2.25,-0.75) J13(2.75,-0.75) J14(3.25,-0.75) K1(-3.25,-1.25) K2(-2.75,-1.25) K3(-2.25,-1.25) K5(-1.25,-1.25) K6(-0.75,-1.25) K7(-0.25,-1.25) K8(0.25,-1.25) K9(0.75,-1.25) K10(1.25,-1.25) K12(2.25,-1.25) K13(2.75,-1.25) K14(3.25,-1.25) L1(-3.25,-1.75) L2(-2.75,-1.75) L3(-2.25,-1.75) L12(2.25,-1.75) L13(2.75,-1.75) L14(3.25,-1.75) M1(-3.25,-2.25) M2(-2.75,-2.25) M3(-2.25,-2.25) M4(-1.75,-2.25) M5(-1.25,-2.25) M6(-0.75,-2.25) M7(-0.25,-2.25) M8(0.25,-2.25) M9(0.75,-2.25) M10(1.25,-2.25) M11(1.75,-2.25) M12(2.25,-2.25) M13(2.75,-2.25) M14(3.25,-2.25) N1(-3.25,-2.75) N2(-2.75,-2.75) N3(-2.25,-2.75) N4(-1.75,-2.75) N5(-1.25,-2.75) N6(-0.75,-2.75) N7(-0.25,-2.75) N8(0.25,-2.75) N9(0.75,-2.75) N10(1.25,-2.75) N11(1.75,-2.75) N12(2.25,-2.75) N13(2.75,-2.75) N14(3.25,-2.75) P1(-3.25,-3.25) P2(-2.75,-3.25) P3(-2.25,-3.25) P4(-1.75,-3.25) P5(-1.25,-3.25) P6(-0.75,-3.25) P7(-0.25,-3.25) P8(0.25,-3.25) P9(0.75,-3.25) P10(1.25,-3.25) P11(1.75,-3.25) P12(2.25,-3.25) P13(2.75,-3.25) P14(3.25,-3.25)
WURTH_6X3P5_TACT_SWITCH
  rect 2.311x1.499 smd: 1(-3.356,0) 2(3.356,0)

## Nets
GND: C1.2 C2.1 C3.2 C4.1 C5.2 C6.2 C7.2 C8.2 C11.2 C13.1 C15.2 C17.1 C18.2 C20.1 C23.2 C25.1 C26.2 C28.2 C29.2 C31.1 C36.2 C37.2 C38.1 C39.2 C40.1 C41.2 C42.1 C43.2 C44.1 C45.1 C46.1 C47.1 C48.1 C49.2 C50.1 C51.2 C52.2 C53.2 C54.2 C55.1 C56.1 C59.2 C70.2 C76.2 C909.2 C914.2 C915.2 C917.2 C922.2 C924.2 C925.1 C927.2 C928.2 C929.1 C931.1 C932.1 C933.1 C934.1 C935.1 C936.1 C937.1 C938.1 C939.1 C940.1 C942.1 C943.2 C944.2 C949.1 C953.1 C954.2 C955.2 C956.2 C957.2 C958.2 C959.2 C960.2 C961.2 C962.2 C964.1 C965.2 J1.61 J1.62 J1.63 J1.64 J2.3 J7.5(SHIELD) J9.2 J10.3 Q1.2(SOURCE) Q2.2(SOURCE) Q3.2(SOURCE) Q4.2(SOURCE) Q5.2(SOURCE) Q6.2(SOURCE) Q7.2(SOURCE) R1.2 R15.2 R17.2 R21.2 R24.2 R26.2 R28.2 R30.2 R32.2 R34.2 R36.2 R39.1 R46.2 R667.1 R668.1 R698.1 R5257.2 R5266.2 R5268.2 R5275.1 R5287.2 S1.1 S2.1 U1.29(VSS) U1.49(P_GND) U5.4(GND1) U5.17(GND2) U5.20(GND3) U5.24(AGND) U5.26(TEST) U5.33(EPAD_GND) U6.4(GND) U7.C5(VSS1) U7.F7(VSS2) U7.K3(VSS3) U7.K8(VSS4) U8.A6(VSS1) U8.C4(VSSQ1) U8.D4(NC33) U8.E7(VSS2) U8.G5(VSS3) U8.H10(VSS4) U8.J5(VSS5) U8.K8(VSS6) U8.N1(NC90) U8.N2(VSSQ2) U8.N5(VSSQ3) U8.P4(VSSQ4) U8.P6(VSSQ5) U14.3(GND) U15.B2(PHMODE) U15.B3(GND_1) U15.B4(SGND) U15.C3(GND_2) U15.D3(GND_3) U15.D4(GND_4) U15.E3(GND_5) U62.5(GND) U62.11(EPAD) U63.3(GND) U64.3(GND) U65.3(GND) U68.3(GND) U69.3(GND) Y1.2(GND) Y2.2(GND)
VCC_3.3V: C51.1 C52.1 C76.1 C900.1 C924.1 C928.1 C949.2 C958.1 L1.1 L7.1 R8.1 R14.1 R86.1 R87.1 R88.1 R5262.2 U8.E6(VCC1) U8.F5(VCC2) U8.J10(VCC3) U8.K9(VCC4) U15.C1(VOUT_1) U15.D1(VOUT_2) U15.D2(VOUT_3) U15.E1(VOUT_4) U15.E2(VOUT_5) U62.9(VIN2) U62.10(VIN1)
VCC_12V: C3.1 C4.2 C917.1 C962.1 J1.1 J1.60 U15.C5(SVIN) U15.D5(VIN_1) U15.E5(VIN_2)
VCCIO_HPS: C1.1 C2.2 C45.2 C46.2 C47.2 C48.2 C53.1 C54.1 C70.1 C909.1 C944.1 C954.1 C956.1 C957.1 C959.1 C960.1 C961.1 J1.2 J1.59 L2.1 L8.1 R2.1 R4.1 R7.1 R83.2 R89.2 R90.2 R102.2 R103.2 R104.2 R105.2 R675.1 R686.1 R687.1 R688.1 R5256.1 R5258.2 R5279.2 R5280.2 R5281.2 R5282.2 R5283.2 R5284.2 R5285.2 R5286.2 R5310.1 R5311.1 R5312.1 R5313.1 R5316.1 U7.D3(VCC1) U7.G4(VCC2) U7.H8(VCC3) U7.J6(VCC4) U8.C6(VCCQ1) U8.M4(VCCQ2) U8.N4(VCCQ3) U8.P3(VCCQ4) U8.P5(VCCQ5) U14.5(VCC) U63.5(VCC) U68.5(VCC) U69.5(VCC)
VDDIM: C49.1 C50.2 U8.C1(NC19) U8.C2(VDDIM)
ACTIVITY_LED: J3.13(YK) L10.2
CARD_PRSTN: J1.52 R1.1
CLK125_NDO_LED_MODE: R35.2 R36.1 U1.41(CLK125_NDO_LED_MODE)
CT0: C5.1 J3.12(CT0)
CT1: C6.1 J3.6(CT1)
CT2: C7.1 J3.1(CT2)
CT3: C8.1 J3.7(CT3)
DC_PGOOD: J1.54 R671.1 U15.C2(PGOOD)
DIP_1: J9.1 R5269.2 R5287.1 U63.1(OE)
E_RX_CLK: R6.1 R33.2 R34.1 U1.35(RX_CLK_PHYAD2)
E_RX_DV: R9.1 R31.2 R32.1 U1.33(RX_DV_CLK125_EN)
E_RXD0: R10.1 R29.2 R30.1 U1.32(RXD0_MODE0)
E_RXD1: R11.1 R27.2 R28.1 U1.31(RXD1_MODE1)
E_RXD2: R12.1 R25.2 R26.1 U1.28(RXD2_MODE2)
E_RXD3: R13.1 R23.2 R24.1 U1.27(RXD3_MODE3)
EMMC_CLK: R53.2 U8.M6(CLK) U8.N7(NC93) U8.P7(NC103)
EMMC_CMD: R54.2 R83.1 R5309.1
EMMC_COMMAND: R5309.2 U8.L1(NC73) U8.L2(NC74) U8.L3(NC75) U8.M5(CMD)
EMMC_D0: R69.2 R5279.1 R5301.1
EMMC_D1: R74.2 R5281.1 R5302.1
EMMC_D2: R67.2 R5280.1 R5303.1
EMMC_D3: R57.2 R5282.1 R5304.1
EMMC_D4: R59.2 R5283.1 R5305.1
EMMC_D5: R79.2 R5284.1 R5306.1
EMMC_D6: R62.2 R5285.1 R5307.1
EMMC_D7: R65.2 R5286.1 R5308.1
EMMC_DAT0: R5301.2 U8.A3(DAT0)
EMMC_DAT1: R5302.2 U8.A4(DAT1)
EMMC_DAT2: R5303.2 U8.A5(DAT2)
EMMC_DAT3: R5304.2 U8.A1(NC1) U8.B2(DAT3)
EMMC_DAT4: R5305.2 U8.A2(NC2) U8.B3(DAT4)
EMMC_DAT5: R5306.2 U8.B4(DAT5) U8.C3(NC20) U8.D1(NC30) U8.D2(NC31)
EMMC_DAT6: R5307.2 U8.B5(DAT6) U8.C5(NC21)
EMMC_DAT7: R5308.2 U8.A8(NC3) U8.B6(DAT7) U8.B7(NC11)
EMMC_RST_N: J10.2 R5314.2 U8.J1(NC61) U8.J2(NC62) U8.J3(NC63) U8.K5(RST_N)
EMMC_RSTN: J10.1 R5278.2 R5314.1
ENET_1.2V_AVDDL: C23.1 C25.2 C931.2 L4.2 U1.4(AVDDL#4) U1.9(AVDDL#9)
ENET_1.2V_AVDLL_PLL: C18.1 C20.2 L3.2 U1.44(AVDDL_PLL)
ENET_1.2V_DVDDL: C29.1 C31.2 C932.2 C933.2 C934.2 C935.2 C936.2 L5.2 U1.14(DVDDL#14) U1.18(DVDDL#18) U1.23(DVDDL#23) U1.26(DVDDL#26) U1.30(DVDDL#30) U1.39(DVDDL#39)
ENET_1.8V_DVDDH: C15.1 C17.2 C938.2 C939.2 L2.2 R16.1 R20.1 R23.1 R25.1 R27.1 R29.1 R31.1 R33.1 R35.1 U1.16(DVDDH#16) U1.34(DVDDH#34) U1.40(DVDDH#40)
ENET_3.3V_AVDDH: C11.1 C13.2 C937.2 L1.2 U1.1(AVDDH#1) U1.12(AVDDH#12)
ENET_GTX_CLK: J1.39 U1.24(GTX_CLK)
ENET_INTN: J1.27 R7.2 U1.38(INT_N/PME_N2)
ENET_LED1: Q6.1(GATE) R20.2 R21.1 U1.17(LED1_PHYAD0/PME_N1)
ENET_LED2: Q4.1(GATE) R16.2 R17.1 U1.15(LED2_PHYAD1)
ENET_MDC: J1.36 R2.2 U1.36(MDC)
ENET_MDIO: J1.35 R4.2 U1.37(MDIO)
ENET_RSET: R15.1 U1.48(ISET)
ENET_RSTN: R5276.2 U1.42(RESET_N)
ENET_RX_CLK: J1.41 R6.2
ENET_RX_DV: J1.42 R9.2
ENET_RXD0: J1.45 R10.2
ENET_RXD1: J1.46 R11.2
ENET_RXD2: J1.49 R12.2
ENET_RXD3: J1.50 R13.2
ENET_TX_EN: J1.40 U1.25(TX_EN)
ENET_TXD0: J1.43 U1.19(TXD0)
ENET_TXD1: J1.44 U1.20(TXD1)
ENET_TXD2: J1.47 U1.21(TXD2)
ENET_TXD3: J1.48 U1.22(TXD3)
ENET_VDD1.2V: C26.1 C28.1 C930.2 L3.1 L4.1 L5.1 R699.1 R5265.2 U62.1(VOUT1) U62.2(VOUT2)
ENET_XI: R19.2 U1.46(XI)
FT232R_3V3OUT: C38.2 C39.1 R42.1 U5.16(3V3OUT)
FT232R_RXD: U5.2(RXD) U65.4(Y)
FT232R_TXD: U5.30(TXD) U63.2(A)
FT232R_VCCIO: C40.2 C41.1 C59.1 C914.1 C943.1 D1.A(ANODE) D2.A(ANODE) R42.2 R50.2 R5269.1 R5271.1 U5.1(VCCIO) U64.5(VCC) U65.5(VCC)
GPIO_RESERVED0: J1.56 R681.1
GPIO_RESERVED1: J1.57 R682.1
HPS_LED0: J1.28 Q1.1(GATE) R681.2
HPS_LED1: J1.37 Q3.1(GATE) R682.2
HPS_LED2: J1.38 Q2.1(GATE)
HPS_OSC_CLK: J1.18 R5289.2
HPS_OSC_CLK_1.8V: C953.2 C955.1 L8.2 R91.1 Y1.4(VCC)
HPS_PB0: J1.31 U14.4(Y)
HPS_PB1: J1.32 U69.4(Y)
HPS_RESETN: J1.53 R675.2 U68.2(A)
I2C1_SCL: J1.34 J2.1 R5256.2
I2C1_SDA: J1.33 J2.2 R686.2
LDO_O: U1.43(LDO_O)
LINK_LED: J3.17(GK) L11.2
LT_INTVCC: R671.2 R5259.1 U15.E4(INTVCC)
MDI_HPS_N0: J3.10(TD0_N) U1.3(TXRXM_A)
MDI_HPS_N1: J3.5(TD1_N) U1.6(TXRXM_B)
MDI_HPS_N2: J3.2(TD2_N) U1.8(TXRXM_C)
MDI_HPS_N3: J3.9(TD3_N) U1.11(TXRXM_D)
MDI_HPS_P0: J3.11(TD0_P) U1.2(TXRXP_A)
MDI_HPS_P1: J3.4(TD1_P) U1.5(TXRXP_B)
MDI_HPS_P2: J3.3(TD2_P) U1.7(TXRXP_C)
MDI_HPS_P3: J3.8(TD3_P) U1.10(TXRXP_D)
MINI_USB_PGND: C940.2 J7.6(SHIELD2) J7.7(SHIELD3) R5266.1
NAND_ADQ0: R52.2 U7.H4(IO0)
NAND_ADQ0_EMMC_CLK: J1.3 R52.1 R53.1
NAND_ADQ1: R55.2 U7.J4(IO1)
NAND_ADQ1_EMMC_CMD: J1.4 R54.1 R55.1
NAND_ADQ2: R56.2 U7.K4(IO2)
NAND_ADQ2_EMMC_D3: J1.8 R56.1 R57.1
NAND_ADQ3: R58.2 U7.K5(IO3)
NAND_ADQ3_EMMC_D4: J1.9 R58.1 R59.1
NAND_ADQ4: R60.2 U7.K6(IO4)
NAND_ADQ4_EMMC_D6: J1.11 R60.1 R62.1
NAND_ADQ5: R64.2 U7.J7(IO5)
NAND_ADQ5_EMMC_D7: J1.12 R64.1 R65.1
NAND_ADQ6: J1.13 U7.K7(IO6)
NAND_ADQ7: J1.14 U7.J8(IO7)
NAND_ADQ8: J1.19 U7.H3(IO8)
NAND_ADQ9: J1.20 U7.J3(IO9)
NAND_ADQ10: J1.21 U7.H5(IO10)
NAND_ADQ11: J1.22 U7.J5(IO11)
NAND_ADQ12: J1.23 U7.H6(IO12)
NAND_ADQ13: J1.24 U7.G6(IO13)
NAND_ADQ14: J1.25 U7.H7(IO14)
NAND_ADQ15: J1.26 U7.G7(IO15)
NAND_ALE: J1.15 U7.C4(ALE)
NAND_CE_N: J11.2 R5315.2 U7.C6(CE#)
NAND_CEN: J1.17 J11.1 R103.1 R5315.1
NAND_CLE: R77.2 U7.D5(CLE)
NAND_CLE_EMMC_D5: J1.10 R77.1 R79.1
NAND_RBN: J1.16 R5258.1 U7.C8(R/B#)
NAND_REN: R72.2 R104.1 U7.D4(RE#)
NAND_REN_EMMC_D1: J1.6 R72.1 R74.1
NAND_WEN: R68.2 R105.1 U7.C7(WE#)
NAND_WEN_EMMC_D0: J1.5 R68.1 R69.1
NAND_WPN: R66.2 R102.1 U7.C3(WP#)
NAND_WPN_EMMC_D2: J1.7 R66.1 R67.1
PB_SW0: C55.2 R89.1 S1.2 U14.2(A)
PB_SW1: C56.2 R90.1 S2.2 U69.2(A)
PHY_25M_3.3V: C925.2 C927.1 L7.2 R18.1 Y2.4(VCC)
PWN_EN: J1.51 R698.2 R5316.2 U15.A3(RUN)
PWR_ENA: R50.1 U5.11(CBUS3)
RJ45_PGND: C942.2 J3.18(GND_TAB#18) J3.19(GND_TAB#19) R5268.1
UART_RESETN: R5270.2 R5271.2 U5.18(R\E\S\E\T\)
UART_RSTN: R5277.2 U64.2(A)
UART_RX: J1.30 R688.2 R5288.2 R5300.1
UART_RX_LED: R49.1 U5.21(CBUS1)
UART_TX: J1.29 R687.2 R5288.1 U65.2(A)
UART_TX_LED: R48.1 U5.22(CBUS0)
USB_UART_5V: C42.2 C43.1 L6.1 U5.19(VCC) U6.6(VBUS)
USB_UART_CON_5V: C44.2 C915.1 J7.1(VBUS) L6.2
USB_UART_DM: C36.1 J7.2(D-) U5.15(USBDM) U6.1(D+)
USB_UART_DP: C37.1 J7.3(D+) U5.14(USBDP) U6.2(D-)
N134005839: J7.4(GND) R46.1
N134005899: D1.C(CATHODE) R48.2
N134005901: D2.C(CATHODE) R49.2
N134231689: D3.A(ANODE) R86.2
N134231691: D3.C(CATHODE) Q1.3(DRAIN)
N134231729: D5.A(ANODE) R88.2
N134231731: D5.C(CATHODE) Q3.3(DRAIN)
N134231769: D4.A(ANODE) R87.2
N134231771: D4.C(CATHODE) Q2.3(DRAIN)
N134232203: R91.2 Y1.1(EN)
N134232219: R5289.1 Y1.3(OUT)
N134273498: C930.1 R39.2 R699.2 U62.3(VFB)
N134273619: R5262.1 U62.7(EN)
N134273639: C929.2 U62.6(SS)
N134273687: R5265.1 U62.4(POK)
N134278396: R5270.1 U64.4(Y)
N134279761: C900.2 R456.2 U15.B1(FB)
N134279929: R5259.2 R5275.2 U15.C4(MODE)
N134279963: C922.1 U15.A2(TRACK/SS)
N134279979: R667.2 U15.A4(FREQ)
N134280029: R456.1 R668.2
N134283374: R5276.1 R5277.1 R5278.1 U68.4(Y)
N134303554: R5300.2 U63.4(Y)
N134317635: R5257.1 R5310.2 U7.G5(LOCK)
N134318194: R18.2 Y2.1(EN)
N134318932: Q4.3(DRAIN) Q5.1(GATE) R5311.2
N134318968: Q6.3(DRAIN) Q7.1(GATE) R5312.2
N134337815: J11.3 R5313.2
N134402864: L10.1 Q7.3(DRAIN)
N134403086: C965.1 J3.14(YA) R8.2
N134403345: C964.2 J3.16(GOA) R14.2
N1343182840: R19.1 Y2.3(OUT)
N1343568020: L11.1 Q5.3(DRAIN)

Pads without a net: J1 55 58; J3 15; NOREF 1; NOREF#7 1; NOREF#9 1; U1 13 45 47; U5 3 5 6 7 8 9 10 12 13 23 25 27 28 29 31 32; U6 3 5; U7 A1 A2 A9 A10 B1 B9 B10 D6 D7 D8 E3 E4 E5 E6 E7 E8 F3 F4 F5 F6 F8 G3 G8 L1 L2 L9 L10 M1 M2 M9 M10; U8 A7 A9 A10 A11 A12 A13 A14 B1 B8 B9 B10 B11 B12 B13 B14 C7 C8 C9 C10 C11 C12 C13 C14 D3 D12 D13 D14 E1 E2 E3 E5 E8 E9 E10 E12 E13 E14 F1 F2 F3 F10 F12 F13 F14 G1 G2 G3 G10 G12 G13 G14 H1 H2 H3 H5 H12 H13 H14 J12 J13 J14 K1 K2 K3 K6 K7 K10 K12 K13 K14 L12 L13 L14 M1 M2 M3 M7 M8 M9 M10 M11 M12 M13 M14 N3 N6 N8 N9 N10 N11 N12 N13 N14 P1 P2 P8 P9 P10 P11 P12 P13 P14; U14 1; U15 A1 A5 B5; U62 8; U64 1; U65 1; U68 1; U69 1

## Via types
v1: diameter 0.61, hole 0.305, TOP to BOTTOM, 505 vias
v2: diameter 0.406, hole 0.203, TOP to BOTTOM, 51 vias

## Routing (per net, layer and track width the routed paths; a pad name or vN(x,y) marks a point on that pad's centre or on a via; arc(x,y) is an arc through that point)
GND: length 127.8
  TOP w0.14: U8.N5 U8.P4
  TOP w0.254: U8.P6 37.21,82.01 v2(37.46,82.26) ; v2(33.7,80.98) 33.6,81.08 33.6,81.38 U8.G5 ; U8.K8 34.51,83.01 v2(34.46,82.96) 34.46,82.39 v2(34.51,82.35) 34.51,81.54 U8.J5 ; U5.24 69.54,85.34 69.39,85.5 v1(69.39,85.63) ; U5.17 73.54,85.3 v1(73.71,85.3) ; v2(33.83,84.53) 33.83,84.35 33.98,84.2 U8.H10 ; v1(63.55,72.47) 63.55,72.15 C964.1 ; U8.C4 U8.D4 v2(32.48,81.01) ; v2(36.48,79.02) U8.N1 U8.N2 ; U8.P4 37.03,80.95 37.49,80.95 v2(37.54,80.9) ; v1(44.37,65.99) 45.79,65.99 45.93,65.85 U1.29 ; U8.A6 v2(29.82,82.01) ; v2(33.04,82.81) 32.86,82.81 32.56,82.51 U8.E7
  TOP w0.305: U7.K3 v2(29.03,55.96) ; v1(70.15,83.64) 70.04,83.75 U5.26 ; U5.4 71.04,82.25 v1(71.29,82.5) 71.54,82.75 U5.20 ; U7.F7 v2(32.65,60.46) ; v1(75.86,85.04) 75.24,85.04 C36.2 ; v2(31.06,62.92) 30.63,62.49 U7.C5 ; v1(75.82,81.97) 75.2,81.97 C37.2 ; R46.2 v1(75.08,77.4) ; U7.K8 v2(33.03,56.26)
  TOP w0.381: v1(14.14,62.79) 13.57,63.36 U14.3 ; R5287.2 v1(62.25,88.55) ; C944.2 v1(67.74,81.23) ; v1(58.11,80.88) 57.9,80.66 C929.1 ; C55.1 v1(12.24,60.66) ; C56.1 v1(8.05,60.66) ; Q3.2 v1(26.64,83.31) ; R15.2 v1(53.26,57.23) ; v1(50.03,72.67) 50.47,72.24 R21.2 ; Q2.2 17.89,84.21 v1(18.16,84.48) ; R26.2 v1(44.24,67.26) ; R17.2 51.74,72.37 v1(52.12,72.75) ; R32.2 v1(44.24,63.45) ; U64.3 v1(69.87,90.63) ; v1(11.5,67.36) 12.1,67.96 C70.2 ; C59.2 v1(73.2,90.85) ; R24.2 v1(44.24,68.66) ; U63.3 v1(67.86,84.02) ; C956.2 8.62,66.46 8.53,66.37 v1(8.53,66.32) ; U69.3 v1(10.86,62.59) ; R34.2 v1(44.24,62.18) ; R28.2 v1(44.37,65.99) ; C943.2 v1(65.32,80.22) ; R36.2 v1(49.58,57.43) ; R30.2 v1(44.37,64.72) ; v1(58.72,73.1) R39.1 ; Q1.2 v1(21.7,84.48) ; v1(64.44,77.53) U65.3
  TOP w0.508: Y1.2 7.22,70.46 7.21,70.46 v1(5.91,70.46) ; Y2.2 v1(50.85,50.24) ; Q4.2 60.44,75.8 v1(59.48,76.76) ; U15.D4 v1(49.27,88.09) ; C955.2 v1(7.3,76.01) ; R668.1 v1(43.48,82.48) ; U15.B4 v1(45.49,88.06) ; U15.E3 v1(50.54,86.82) ; C953.1 8.25,75.76 v1(8.25,75.8) ; U15.B3 v1(45.46,85.55) ; U15.B2 v1(45.46,84.28) ; U15.D3 v1(49.27,86.82) ; Q5.2 v1(64.25,76.79) ; U15.C3 v1(46.73,86.82)
  BOTTOM w0.254: v1(64.31,72.47) 64.31,72.09 63.99,71.77 C964.1 ; U6.4 74.09,82.42 v1(74.34,82.17)
  BOTTOM w0.305: v1(7.72,69.27) 7.58,69.41 C909.2
  BOTTOM w0.381: v2(32.05,83.77) 31.73,83.45 C54.2 ; v1(23.87,75.64) 23.74,75.52 R698.1 ; C959.2 37.4,81.04 v2(37.54,80.9) ; v1(9.11,64.82) 9.11,65.41 9.48,65.77 U68.3 ; C48.1 28.32,59.51 v1(28.09,59.29) ; v1(57.2,62.97) 56.69,63.48 C23.2 ; v1(26.06,61.55) 26.18,61.67 C47.1 ; v2(37.46,82.26) 38.02,82.82 C960.2 ; C2.1 23.14,78.95 v1(23.54,78.54) ; v1(5.89,76.69) 8.12,76.69 8.4,76.41 R1.2 ; v2(33.7,80.98) 33.97,81.24 C958.2 ; v2(33.04,82.81) 32.95,82.9 C52.2 ; C53.2 v1(40.05,78.56) ; v2(32.65,60.46) 32.65,59.83 32.3,59.49 R5257.2
  BOTTOM w0.508: C51.2 v1(35.35,86.97) ; C914.2 73.22,80.57 v1(72.44,81.36) ; C4.1 8.17,78.95 v1(7.97,79.15) ; C6.2 v1(64.35,49.71) ; C38.1 75.37,85.53 v1(75.86,85.04) ; C50.1 29.97,79.15 v1(29.33,79.78) ; C20.1 49.7,57.56 v1(49.58,57.43) ; v1(22.78,84.41) 22.49,84.12 C1.2 22.05,82.25 v1(20.87,82.25) ; R5275.1 48.89,88.47 v1(49.27,88.09) ; v1(33.7,57.89) 34.45,57.89 C46.1 ; C13.1 v1(56.71,67.9) ; v1(50.03,72.67) 49.7,72.34 C15.2 ; C11.2 v1(57.58,69.29) ; C927.2 v1(42.97,57.8) ; C924.2 v1(42.31,51.58) ; C39.2 73.2,88.34 v1(73.96,89.11) ; v1(26.59,82.5) 26.06,82.5 25.87,82.69 C961.2 24.7,82.8 v1(24.7,84.24) ; R667.1 45.4,88.15 v1(45.49,88.06) ; v1(7.96,84.36) C962.2 v1(6.83,83.09) ; C18.2 v1(50.52,58.12) ; v1(6.78,80.22) 7.46,80.22 C3.2 7.98,80.74 7.41,81.31 v1(6.73,81.31) ; C7.2 v1(64.5,67.85) ; C922.2 45.34,85.42 v1(45.46,85.55) ; C957.2 v1(37.08,57.38) ; C40.1 69.54,80.75 v1(70.15,81.36) 71.17,80.34 C41.2 ; C5.2 v1(61.78,49.58) ; v1(68.42,86.24) 68.42,87.06 C43.2 ; C49.2 29.82,80.83 v2(29.82,82.01) ; v1(30.41,55.98) 30.81,56.38 C45.1 ; Q6.2 v1(62.34,76.79) ; C925.1 v1(44.43,56.91) ; C29.2 v1(48.26,73.48) ; v1(69.39,85.63) 69.52,85.75 C42.1 ; C8.2 v1(62.21,67.85) ; Q7.2 v1(66.15,76.79)
  vias: v1(5.89,93.55) v1(5.89,90.38) v1(5.89,87.84) v1(5.89,85.3) v1(5.89,80.22) v1(5.86,78.13) v1(5.89,75.14) v1(5.89,72.6) v1(5.89,67.52) v1(5.89,64.98) v1(5.89,62.44) v1(5.89,59.9) v1(5.89,57.36) v1(5.89,54.82) v1(5.89,52.28) v1(5.89,49.61) v1(5.97,82.71) v1(7.79,52.4) v1(7.79,50.75) v1(8.43,93.55) v1(8.43,49.61) v1(10.23,69.27) v1(10.66,75.82) v1(10.84,52.4) v1(10.84,50.75) v1(10.97,93.55) v1(10.97,49.61) v1(11.22,76.91) v1(12.62,52.53) v1(12.62,50.88) v1(13.51,93.55) v1(13.51,49.61) v1(14.88,62) v1(14.88,61.27) v1(14.88,60.53) v1(15.24,81.59) v1(15.16,80.72) v1(15.16,79.83) v1(15.16,63.93) v1(15.16,62.84) v1(15.41,65.56) v1(15.74,61.27) v1(15.85,78.06) v1(15.82,64.93) v1(15.77,60.51) v1(15.87,82.04) v1(15.95,71.43) v1(16.05,93.55) v1(16.05,49.61) v1(16.18,52.66) v1(16.18,50.88) v1(16.25,65.53) v1(16.51,78.49) v1(16.53,72.52) v1(16.56,62.87) v1(16.56,62.11) v1(16.58,61.34) v1(16.61,60.53) v1(16.68,82.02) v1(16.68,80.52) v1(16.68,79.76) v1(16.81,73.79) v1(18.59,93.55) v1(18.59,49.61) v1(21.13,93.55) v1(21.13,49.61) v1(22.09,63.71) v1(23.67,93.55) v1(23.67,49.61) v1(26.21,93.55) v1(26.21,49.61) v1(28.75,93.55) v1(28.75,49.61) v1(31.29,93.55) v1(31.29,49.61) v1(33.83,93.55) v1(33.83,49.61) v1(34.72,66.32) v1(34.97,56.64) v1(36.37,93.55) v1(36.37,49.61) v1(38.91,93.55) v1(38.91,49.61) v1(39.14,61.12) v1(41.45,93.55) v1(41.45,49.61) v1(43.99,93.55) v1(43.99,49.61) v1(46.53,93.55) v1(46.53,49.61) v1(47.16,57.33) v1(47.35,50.44) v1(47.49,78.56) v1(47.49,77.29) v1(47.93,67.26) v1(47.93,65.1) v1(47.93,63.2) v1(48.76,78.56) v1(48.76,77.29) v1(49.07,93.55) v1(49.07,49.61) v1(49.83,67.26) v1(49.83,65.1) v1(49.83,62.94) v1(50.97,60.78) v1(51.25,79.61) v1(51.86,93.55) v1(51.89,49.66) v1(51.99,67.26) v1(51.99,65.1) v1(51.99,62.94) v1(52.12,60.66) v1(53.13,51.89) v1(53.97,77.68) v1(53.97,76.66) v1(54.48,87.45) v1(54.48,86.18) v1(54.86,77.68) v1(54.86,76.66) v1(55.04,52.78) v1(55.29,57.36) v1(55.62,77.17) v1(55.75,87.45) v1(55.75,86.18) v1(55.75,84.91) v1(56.26,77.68) v1(56.26,76.66) v1(56.61,66.27) v1(56.61,64.9) v1(56.69,59.13) v1(57.58,52.4) v1(57.68,67.77) v1(57.88,60.91) v1(58.85,51.26) v1(59,58.85) v1(59.91,49.63) v1(59.99,93.55) v1(60.19,67.67) v1(62.53,93.55) v1(65.07,93.55) v1(67.61,93.55) v1(68.5,76.66) v1(68.5,75.64) v1(69.52,77.04) v1(70.15,93.55) v1(70.53,77.04) v1(71.55,76.66) v1(71.55,75.64) v1(72.06,93.47) v1(72.44,83.64) v1(72.97,93.47) v1(74.01,93.45) v1(74.93,93.42) v1(75.26,89.74) v1(76.25,89.74) v1(76.25,88.6) v1(77.39,75.64) v1(78.28,93.55) v1(79.29,75.26) v1(80.18,76.15) v1(80.31,93.55)
VCC_3.3V: length 16.8
  TOP w0.254: 33.03,82.13 32.98,82.08 U8.F5 33,81.48 33,81.07 v2(33.07,81) ; 33.03,82.13 32.6,82.13 U8.E6 ; 33.03,82.13 v2(33.07,82.17) ; v2(34.36,84.51) 34.48,84.39 U8.J10 ; v2(34.46,83.51) U8.K9 v2(35.48,83.51) ; R14.1 62.49,71.77 v1(62.02,72.24)
  TOP w0.381: v1(19.1,92.13) 18.33,92.13 R87.1 ; R88.1 v1(23.54,92.13) ; R86.1 v1(21.26,92.13)
  TOP w0.508: 47.63,80.86 C900.1
  BOTTOM w0.254: R14.1 62.78,71.9 v1(62.78,72.47)
  BOTTOM w0.381: 33.07,81.6 v2(33.07,82.17) ; 33.07,81.6 C958.1 ; 33.07,81.6 v2(33.07,81) ; v2(34.36,84.51) 34.36,84.2 34.01,83.85 C52.1 34.18,83.51 v2(34.46,83.51)
  BOTTOM w0.508: L7.1 41.19,53.36 C924.1 v1(41.07,54.61) ; C51.1 35.35,83.63 v2(35.48,83.51) ; L1.1 v1(55.93,70.31)
  vias: v1(53.97,82.37) v1(53.97,81.49) v1(54.99,82.37) v1(54.99,81.49) v1(56,82.37) v1(56,81.49)
VCC_12V:
  vias: v1(9.57,85.93) v1(9.62,85.12) v1(9.65,84.33) v1(10.71,85.96) v1(10.74,85.12) v1(10.74,84.36) v1(17.7,63.95) v1(18.77,63.25) v1(22.04,86.77) v1(22.91,86.77) v1(53.84,90.88) v1(53.84,89.87) v1(53.84,88.85) v1(54.86,90.88) v1(54.86,89.87) v1(54.86,88.85) v1(55.88,90.88) v1(55.88,89.87) v1(55.88,88.85)
VCCIO_HPS: length 59.3
  TOP w0.14: U8.N4 U8.P3
  TOP w0.254: v2(32.05,82.76) 32.05,82.5 31.55,82.01 U8.C6 ; v2(37.53,80.19) 37.46,80.19 37.15,80.51 U8.P3 ; U8.M4 U8.N4 ; U8.P5 v2(37.69,81.51)
  TOP w0.305: R688.1 R5256.1 12.76,72.55 13.94,72.55 13.97,72.52 v1(14.14,72.52) ; U7.H8 33.42,58.83 v1(33.65,58.83) ; v2(28.44,61.64) U7.D3 ; U7.J6 v2(31.85,57.23) ; U7.G4 v2(29.43,58.84)
  TOP w0.381: v1(44.42,58.18) R4.1 R7.1 ; R5313.1 v1(20.54,57.67) ; R90.2 v1(8.75,62.61) ; v1(41.91,60.91) R2.1 ; R5282.2 v1(30.78,72.16) ; U14.5 12.27,67.01 C70.1 12.18,67.07 11.68,66.58 v1(11.53,66.58) ; R5311.1 v1(60.44,70.88) ; R89.2 v1(12.21,62.05) ; R5285.2 v1(28.24,72.21) ; v1(65.22,81.23) C944.1 66.02,81.83 65.14,82.72 U63.5 ; R83.2 v1(34.21,72.09) ; U69.5 9.56,66.44 9.51,66.49 C956.1 v1(9.51,67.72) ; v1(20.57,52.59) R103.2 ; v1(29.51,72.19) R5283.2
  TOP w0.508: v1(11.43,81.23) 10.97,80.77 C954.1 10.24,79.65 L8.1
  BOTTOM w0.305: v1(7.74,68.43) 7.65,68.52 C909.1 7.01,67.47 7.4,67.07 U68.5
  BOTTOM w0.381: 24,76.85 R5316.1 ; 24,76.85 24,77.68 24.35,78.03 v1(24.35,78.56) ; 24,76.85 R675.1 ; C47.2 27.88,61.64 v2(28.44,61.64) ; C959.1 36.96,80.19 v2(37.53,80.19) ; v1(34.21,72.09) R83.2 ; v1(39.95,80.39) 39.65,80.09 C53.1 38.55,80.44 v2(38.55,80.95) ; v1(23.69,72.67) 23.62,72.75 R686.1 ; R5258.2 v1(34.53,60.71) ; v1(30.15,65.48) R104.2 ; v2(32.05,82.76) 31.86,82.57 C54.1 ; R5285.2 v1(28.24,72.21) ; R5282.2 v1(30.78,72.16) ; R5311.1 v1(61.39,70.06) ; v2(29.43,58.84) 29.43,58.85 29.8,59.22 C48.2 R5310.1 ; R5283.2 v1(29.51,72.19) ; R102.2 v1(27.61,65.48) ; v1(31.42,65.48) R105.2 ; v1(25.24,72.72) 23.96,71.44 R687.1 ; C960.1 37.98,81.51 v2(37.69,81.51) ; R5279.2 v1(32.05,72.19)
  BOTTOM w0.508: C45.2 31.81,57.27 v2(31.85,57.23) ; C46.2 34.43,58.83 v1(33.65,58.83) ; C957.1 v1(37.13,58.91) ; v1(54.05,73.03) 54.05,73.26 v1(53.56,73.74) L2.1
  vias: v1(11.5,64.11) v1(11.58,63.3) v1(23.82,79.68) v1(24.61,79.66)
VDDIM: length 3.7
  TOP w0.254: v2(31.67,78.95) 31.48,79.14 U8.C1 U8.C2
  BOTTOM w0.508: v2(31.67,78.95) 31.47,79.15 C50.2 30.95,79.7 31.29,80.04 C49.1
ACTIVITY_LED: length 27.3
  BOTTOM w0.254: J3.13 76.37,61.42 74.09,59.13 67.86,59.13 66.21,60.78 66.21,69.87 L10.2
CARD_PRSTN: length 3.1
  BOTTOM w0.142: R1.1 11.6,76.41 12.03,76.83 J1.52
CLK125_NDO_LED_MODE: length 4.2
  TOP w0.142: U1.41 49.08,60.67 48.94,60.53 48.94,59.71 R36.1 R35.2
CT0: length 2.5
  BOTTOM w0.508: C5.1 60.89,51.76 60.88,51.77 J3.12
CT1: length 3.4
  BOTTOM w0.508: C6.1 63.46,52.75 63.42,52.78 J3.6
CT2: length 4.7
  BOTTOM w0.508: C7.1 63.61,66.7 63.42,66.51 J3.1
CT3: length 3.7
  BOTTOM w0.508: C8.1 61.32,66.86 60.88,66.41 J3.7
DC_PGOOD: length 60.1
  TOP w0.142: U15.C2 v1(46.73,84.28)
  L3_SIG w0.155: v1(46.73,84.28) 46.73,85.65 44.93,87.45 43.48,87.45 43.2,87.73 25.52,87.73 22.2,91.06 16.38,91.06 15.95,90.63 15.95,84.99 11.6,80.65 8.73,80.65 7.32,79.23 7.32,79.21 7.26,79.15 v1(7.26,78.64)
  BOTTOM w0.142: v1(46.73,84.28) 46.74,84.29 R671.1 ; J1.54 11.77,77.33 11.63,77.47 10.71,77.47 10.28,77.04 8.63,77.04 7.62,78.06 7.62,78.29 v1(7.26,78.64)
DIP_1: length 11.1
  TOP w0.142: J9.1 63.84,92.12 R5287.1 R5269.2 63.84,86.15 65.73,84.25 65.73,83.22 66.23,82.72 U63.1
E_RX_CLK: length 8.8
  TOP w0.142: v1(41.83,62.18) R33.2 41.51,62.82 42.02,62.82 R34.1 43.29,61.55 44.75,61.55 46.06,62.85 U1.35
  BOTTOM w0.142: v1(41.83,62.18) R33.2
E_RX_DV: length 8.5
  TOP w0.142: v1(41.83,63.45) R31.2 41.39,63.96 42.15,63.96 R32.1 43.16,62.94 44.5,62.94 45.41,63.85 U1.33
  BOTTOM w0.142: v1(41.83,63.45) R31.2
E_RXD0: length 8.4
  TOP w0.142: U1.32 45.02,64.35 44.75,64.09 43.29,64.09 R30.1 42.02,65.36 41.51,65.36 R29.2 v1(41.83,64.72)
  BOTTOM w0.142: v1(41.83,64.72) R29.2
E_RXD1: length 8.1
  TOP w0.142: v1(41.7,65.99) R27.2 41.39,66.5 42.15,66.5 R28.1 43.29,65.36 44.62,65.36 45.13,64.85 U1.31
  BOTTOM w0.142: v1(41.7,65.99) R27.2
E_RXD2: length 8
  TOP w0.142: v1(41.7,67.26) R25.2 41.39,67.77 42.15,67.77 R26.1 43.29,66.63 44.5,66.63 44.77,66.35 U1.28
  BOTTOM w0.142: v1(41.7,67.26) R25.2
E_RXD3: length 8.5
  TOP w0.142: U1.27 45.67,66.85 44.62,67.9 43.42,67.9 R24.1 42.02,69.29 41.51,69.29 R23.2 v1(41.73,68.66)
  BOTTOM w0.142: v1(41.73,68.66) R23.2
EMMC_CLK: length 18
  TOP w0.142: v1(35.84,78.82) 36.01,78.64 36.7,78.64 38.12,80.06 38.12,82.17 37.66,82.63 37.23,82.63 37.11,82.51 U8.P7 U8.N7 U8.M6
  BOTTOM w0.142: R53.2 33.96,70.39 35.84,72.27 v1(35.84,78.82)
EMMC_CMD: length 5.8
  TOP w0.142: R54.2 34.18,70.34 33.32,71.21 33.32,73.04 R83.1 R5309.1
EMMC_COMMAND: length 6.6
  TOP w0.142: R5309.2 34.21,76.71 35.1,77.6 35.1,79.02 35.48,79.4 U8.L1 U8.L2 U8.L3 35.48,81.37 35.61,81.51 U8.M5
EMMC_D0: length 6.6
  BOTTOM w0.142: R69.2 31.42,73.48 31.86,73.93 R5279.1 R5301.1
EMMC_D1: length 6.6
  BOTTOM w0.142: R74.2 30.15,73.48 30.59,73.93 R5281.1 R5302.1
EMMC_D2: length 7.3
  BOTTOM w0.142: R67.2 27.07,69.76 27.07,73.46 27.54,73.93 R5280.1 R5303.1
EMMC_D3: length 6
  TOP w0.142: R57.2 30.15,71.08 30.15,73.61 30.46,73.93 R5282.1 R5304.1
EMMC_D4: length 5.5
  TOP w0.142: R5305.1 R5283.1 29.12,73.54 28.93,73.54 28.8,73.41 R59.2
EMMC_D5: length 7.3
  BOTTOM w0.142: R5306.1 R5284.1 33.51,73.93 33.19,73.61 33.19,69.74 R79.2
EMMC_D6: length 6.1
  TOP w0.142: R62.2 26.36,72.5 27.79,73.93 R5285.1 R5307.1
EMMC_D7: length 6.7
  BOTTOM w0.142: R5308.1 R5286.1 29.19,73.93 28.88,73.61 R65.2
EMMC_DAT0: length 8.9
  TOP w0.142: U8.A3 28.94,80.51 v1(28.67,80.24)
  BOTTOM w0.142: R5301.2 30.46,77.93 28.31,77.93 28.16,78.07 28.16,79.73 v1(28.67,80.24)
EMMC_DAT1: length 9.2
  TOP w0.142: U8.A4 28.65,81.01 v1(27.86,80.22)
  BOTTOM w0.142: v1(27.86,80.22) 27.76,80.11 27.76,77.52 27.99,77.29 29.83,77.29 R5302.2
EMMC_DAT2: length 9.5
  TOP w0.142: U8.A5 29.72,81.51 29.38,81.84 28.29,81.84 v1(28.14,81.99)
  BOTTOM w0.142: R5303.2 27.8,76.34 26.95,77.19 26.95,80.72 28.14,81.92 v1(28.14,81.99)
EMMC_DAT3: length 5.2
  TOP w0.142: U8.B2 U8.A1 30.48,79.5 31.67,78.31 31.67,77.42 30.78,76.53 R5304.2
EMMC_DAT4: length 8.9
  TOP w0.142: R5305.2 29.51,76.86 29.2,77.17 27.73,77.17 27.48,77.42 27.48,78.79 27.89,79.2 29.56,79.2 30.37,80.01 U8.A2 U8.B3
EMMC_DAT5: length 6
  TOP w0.142: v1(32.41,78.9) 32.18,79.12 32.18,79.31 U8.D1 U8.D2 U8.C3 U8.B4
  BOTTOM w0.142: R5306.2 32.43,78.12 32.43,78.87 v1(32.41,78.9)
EMMC_DAT6: length 14.3
  TOP w0.142: U8.B5 U8.C5 31.74,81.51 v2(31.97,81.74) ; R5307.2 26.97,77.1 26.97,81.66 28.03,82.72 28.91,82.72 v2(29.33,83.14)
  L3_SIG w0.155: v2(29.33,83.14) 29.84,83.64 30.4,83.64 30.78,83.26 30.78,82.93 v2(31.97,81.74)
EMMC_DAT7: length 11.1
  TOP w0.142: U8.B6 U8.B7 U8.A8 30.47,83.01 v2(29.89,83.01)
  BOTTOM w0.142: v2(29.89,83.01) 27.35,80.47 27.35,77.37 27.82,76.9 28.95,76.9 R5308.2
EMMC_RST_N: length 33.2
  TOP w0.142: U8.K5 34.98,81.01 U8.J3 U8.J2 U8.J1 34.48,79.11 v1(34.21,78.84) ; v1(16.81,87.58) R5314.2 16.11,88.41 15.54,88.98 12.92,88.98 J10.2
  L6_SIG w0.155: v1(34.21,78.84) 33.17,79.89 32.46,79.89 31.03,81.31 31.03,84 26.54,88.5 17.73,88.5 v1(16.81,87.58)
EMMC_RSTN: length 44.1
  TOP w0.142: J10.1 11.15,89.74 15.67,89.74 16.11,89.3 R5314.1 v1(16.81,90.5)
  L3_SIG w0.155: v1(16.81,90.5) 17.45,89.87 17.45,85.68 11.82,80.05 10.17,80.05 9.06,78.95 9.06,75.85 10.74,74.17 10.74,69.04 10.05,68.35 10.05,66.88 8.17,65 v1(6.96,65)
  BOTTOM w0.142: v1(6.96,65) 6.71,64.76 R5278.2
ENET_1.2V_AVDDL: length 2.1
  TOP w0.254: U1.9 v1(54.38,66.35) ; U1.4 v1(54.17,63.85)
ENET_1.2V_AVDLL_PLL: length 7.7
  TOP w0.254: U1.44 50.58,61.28 50.21,60.91 v1(50.21,60.78)
  BOTTOM w0.508: L3.2 53.26,58.24 51.86,59.64 C18.1 51.16,59.2 C20.2 50.21,59.71 v1(50.21,60.78)
ENET_1.2V_DVDDL: length 11.3
  TOP w0.254: v1(45.46,65.36) 45.51,65.36 45.52,65.35 U1.30 ; U1.26 45.93,67.35 v1(45.51,67.77) ; U1.39 48.08,61.1 48.03,61.05 48.03,60.86 v1(47.72,60.56)
  TOP w0.305: U1.23 47.58,69 47.16,69.42 v1(46.78,69.42) ; U1.18 50.08,69.67 v1(50.08,69.67) ; v1(52.88,69.67) 52.08,68.88 U1.14
  BOTTOM w0.381: v1(47.72,60.56) 47.57,60.71 C31.2
  BOTTOM w0.508: C935.2 50.06,69.65 v1(50.08,69.67) ; v1(52.88,69.67) 52.6,69.4 C936.2 ; C933.2 45.45,67.71 v1(45.51,67.77) ; C932.2 v1(45.46,65.36)
  vias: v1(46.02,71.58)
